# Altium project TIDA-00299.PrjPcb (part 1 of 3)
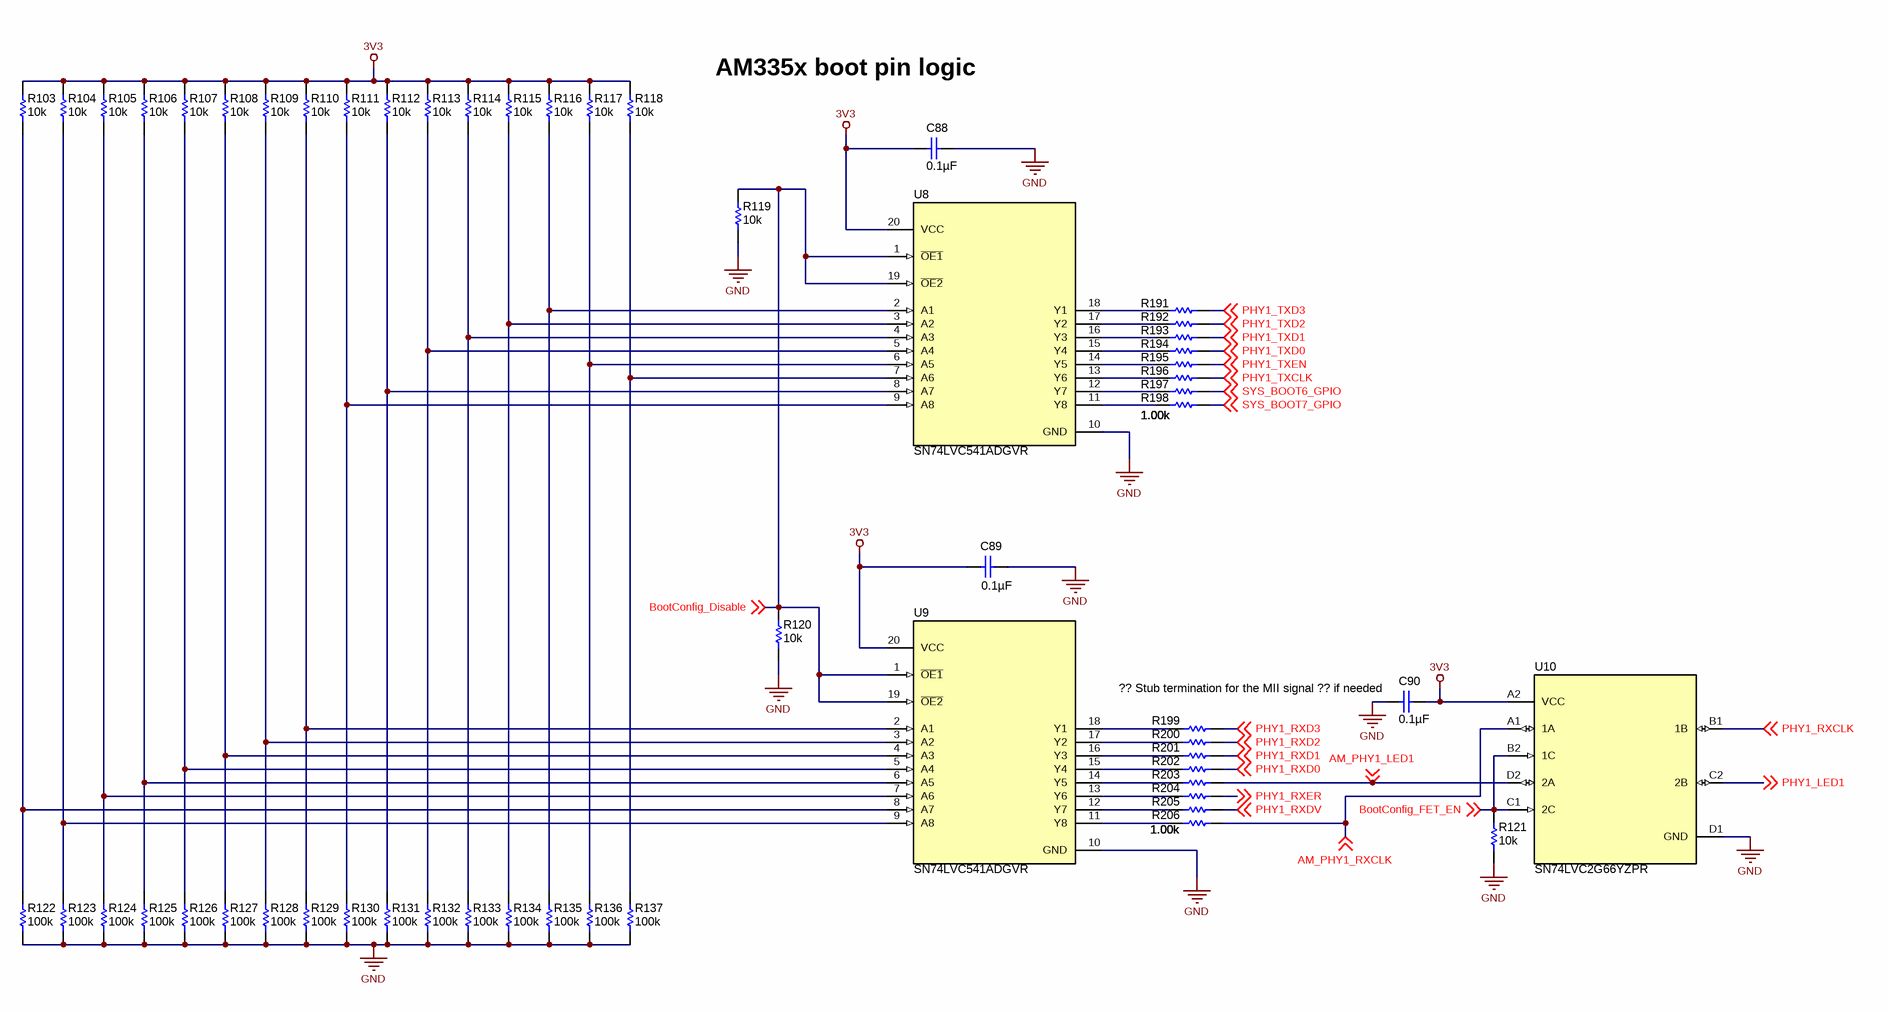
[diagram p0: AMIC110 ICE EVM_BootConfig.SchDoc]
TID: TIDA-00299; TechSupport: http://www.ti.com/support; SCH_Rev: E2.1; PRJ_Title1: Multi-Protocol Industrial Ethernet Reference Design; PRJ_Title: Cost Optimized Robust EtherCAT Slave and; PRJ_Number: TIDA-00299; PRJ_Engineer: Mogensen/Staebler; PRJ_Customer: Public Release; PCB_Rev: E2; PCB_Layout: Klaus Hacker; EVM_Orderable: N/A; CopyrightYear: 2017
10 sheets, 504 parts. Net scope: global (net labels, ports and power ports of the same name join across sheets).
Board file: MS_TI_AMIC110_ICE_EVM_BRD_REV1.1.PcbDoc
Sheets:
  AMIC110 ICE EVM_BootConfig.SchDoc
  AMIC110 ICE EVM_CS.SchDoc
  AMIC110 ICE EVM_HW.SchDoc
  AMIC110 ICE EVM_Interfaces.SchDoc
  AMIC110 ICE EVM_Led.SchDoc
  AMIC110 ICE EVM_Memory.SchDoc
  AMIC110 ICE EVM_PHY.SchDoc
  AMIC110 ICE EVM_Power.SchDoc
  AMIC110 ICE EVM_PS.SchDoc
  AMIC110 ICE EVM_SC_0.SchDoc

## Sheet AMIC110 ICE EVM_BootConfig.SchDoc
size 431 x 279 mm; Date: Not shown in title block; ApprovedBy: Not shown in title block; CheckedBy: Not shown in title block; Author: Not shown in title block; CompanyName: Not shown in title block; Engineer: Not shown in title block; Organization: Not shown in title block; Address1: Not shown in title block; Address2: Not shown in title block; Address3: Not shown in title block; Address4: Not shown in title block; DocumentNumber: 1; Revision: Use project parameter SCH_Rev; SheetNumber: 9; SheetTotal: 1; PageSetup: Record=PageOptions¦CenterHorizontal=True¦CenterVertical=True¦PrintScale=1.00¦XCorrection=1.00¦YCorrection=1.00¦PrintKind=0¦BorderSize=5000000¦LeftOffset=0¦BottomOffset=0¦Orientation=2¦PaperLength=1000¦PaperWidth=1000¦Scale=100¦PaperSource=15¦PrintQuality=600¦MediaType=1¦DitherType=10¦PaperKind=Letter¦PrintScaleMode=1

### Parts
C88  ValueDisplayed: 0.1µF  [0402]  (hidden comment: 885012205037)
C89  ValueDisplayed: 0.1µF  [0402L]  (hidden comment: 885012205037)
C90  ValueDisplayed: 0.1µF  [0402L]  (hidden comment: 885012205037)
R103  ValueDisplayed: 10k  [0402L]  (hidden comment: CRCW040210K0JNED)
R104  ValueDisplayed: 10k  [0402L]  (hidden comment: CRCW040210K0JNED)
R105  ValueDisplayed: 10k  [0402L]  (hidden comment: CRCW040210K0JNED)
R106  ValueDisplayed: 10k  [0402L]  (hidden comment: CRCW040210K0JNED)
R107  ValueDisplayed: 10k  [0402L]  (hidden comment: CRCW040210K0JNED)
R108  ValueDisplayed: 10k  [0402L]  (hidden comment: CRCW040210K0JNED)
R109  ValueDisplayed: 10k  [0402L]  (hidden comment: CRCW040210K0JNED)
R110  ValueDisplayed: 10k  [0402L]  (hidden comment: CRCW040210K0JNED)
R111  ValueDisplayed: 10k  [0402L]  (hidden comment: CRCW040210K0JNED)
R112  ValueDisplayed: 10k  [0402L]  (hidden comment: CRCW040210K0JNED)
R113  ValueDisplayed: 10k  [0402L]  (hidden comment: CRCW040210K0JNED)
R114  ValueDisplayed: 10k  [0402L]  (hidden comment: CRCW040210K0JNED)
R115  ValueDisplayed: 10k  [0402L]  (hidden comment: CRCW040210K0JNED)
R116  ValueDisplayed: 10k  [0402L]  (hidden comment: CRCW040210K0JNED)
R117  ValueDisplayed: 10k  [0402L]  (hidden comment: CRCW040210K0JNED)
R118  ValueDisplayed: 10k  [0402L]  (hidden comment: CRCW040210K0JNED)
R119  ValueDisplayed: 10k  [0402]  (hidden comment: CRCW040210K0JNED)
R120  ValueDisplayed: 10k  [0402L]  (hidden comment: CRCW040210K0JNED)
R121  ValueDisplayed: 10k  [0402L]  (hidden comment: CRCW040210K0JNED)
R122  ValueDisplayed: 100k  [0402L]  (hidden comment: CRCW0402100KJNED)
R123  ValueDisplayed: 100k  [0402L]  (hidden comment: CRCW0402100KJNED)
R124  ValueDisplayed: 100k  [0402L]  (hidden comment: CRCW0402100KJNED)
R125  ValueDisplayed: 100k  [0402L]  (hidden comment: CRCW0402100KJNED)
R126  ValueDisplayed: 100k  [0402L]  (hidden comment: CRCW0402100KJNED)
R127  ValueDisplayed: 100k  [0402L]  (hidden comment: CRCW0402100KJNED)
R128  ValueDisplayed: 100k  [0402L]  (hidden comment: CRCW0402100KJNED)
R129  ValueDisplayed: 100k  [0402L]  (hidden comment: CRCW0402100KJNED)
R130  ValueDisplayed: 100k  [0402L]  (hidden comment: CRCW0402100KJNED)
R131  ValueDisplayed: 100k  [0402L]  (hidden comment: CRCW0402100KJNED)
R132  ValueDisplayed: 100k  [0402L]  (hidden comment: CRCW0402100KJNED)
R133  ValueDisplayed: 100k  [0402L]  (hidden comment: CRCW0402100KJNED)
R134  ValueDisplayed: 100k  [0402L]  (hidden comment: CRCW0402100KJNED)
R135  ValueDisplayed: 100k  [0402L]  (hidden comment: CRCW0402100KJNED)
R136  ValueDisplayed: 100k  [0402L]  (hidden comment: CRCW0402100KJNED)
R137  ValueDisplayed: 100k  [0402L]  (hidden comment: CRCW0402100KJNED)
R191  ValueDisplayed: 1.00k  [0201L]  (hidden comment: CRCW02011K00FKED)
R192  ValueDisplayed: 1.00k  [0201L]  (hidden comment: CRCW02011K00FKED)
R193  ValueDisplayed: 1.00k  [0201L]  (hidden comment: CRCW02011K00FKED)
R194  ValueDisplayed: 1.00k  [0201L]  (hidden comment: CRCW02011K00FKED)
R195  ValueDisplayed: 1.00k  [0201L]  (hidden comment: CRCW02011K00FKED)
R196  ValueDisplayed: 1.00k  [0201L]  (hidden comment: CRCW02011K00FKED)
R197  ValueDisplayed: 1.00k  [0201L]  (hidden comment: CRCW02011K00FKED)
R198  ValueDisplayed: 1.00k  [0201L]  (hidden comment: CRCW02011K00FKED)
R199  ValueDisplayed: 1.00k  [0201L]  (hidden comment: CRCW02011K00FKED)
R200  ValueDisplayed: 1.00k  [0201L]  (hidden comment: CRCW02011K00FKED)
R201  ValueDisplayed: 1.00k  [0201L]  (hidden comment: CRCW02011K00FKED)
R202  ValueDisplayed: 1.00k  [0201L]  (hidden comment: CRCW02011K00FKED)
R203  ValueDisplayed: 1.00k  [0201L]  (hidden comment: CRCW02011K00FKED)
R204  ValueDisplayed: 1.00k  [0201L]  (hidden comment: CRCW02011K00FKED)
R205  ValueDisplayed: 1.00k  [0201L]  (hidden comment: CRCW02011K00FKED)
R206  ValueDisplayed: 1.00k  [0201L]  (hidden comment: CRCW02011K00FKED)
U8  SN74LVC541ADGVR  [DGV0020A_L]
U9  SN74LVC541ADGVR  [DGV0020A_L]
U10  SN74LVC2G66YZPR  [YZP0008ADAD]

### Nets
3V3: C88.1 C89.2 C90.2 R103.2 R104.2 R105.2 R106.2 R107.2 R108.2 R109.2 R110.2 R111.2 R112.2 R113.2 R114.2 R115.2 R116.2 R117.2 R118.2 U8.20(VCC) U9.20(VCC) U10.A2(VCC)
GND: C88.2 C89.1 C90.1 R119.1 R120.1 R121.1 R122.1 R123.1 R124.1 R125.1 R126.1 R127.1 R128.1 R129.1 R130.1 R131.1 R132.1 R133.1 R134.1 R135.1 R136.1 R137.1 U8.10(GND) U9.10(GND) U10.D1(GND)
AM_PHY1_LED1: R203.2 U10.D2(2A) ; off-sheet AM_PHY1_LED1
AM_PHY1_RXCLK: R206.2 U10.A1(1A) ; off-sheet AM_PHY1_RXCLK
BootConfig_Disable: R119.2 R120.2 U8.1(~{OE1}) U8.19(~{OE2}) U9.1(~{OE1}) U9.19(~{OE2}) ; off-sheet BootConfig_Disable
BootConfig_FET_EN: R121.2 U10.B2(1C) U10.C1(2C) ; off-sheet BootConfig_FET_EN
PHY1_LED1: U10.C2(2B) ; off-sheet PHY1_LED1
PHY1_RXCLK: U10.B1(1B) ; off-sheet PHY1_RXCLK
PHY1_RXD0: R202.2 ; off-sheet PHY1_RXD0
PHY1_RXD1: R201.2 ; off-sheet PHY1_RXD1
PHY1_RXD2: R200.2 ; off-sheet PHY1_RXD2
PHY1_RXD3: R199.2 ; off-sheet PHY1_RXD3
PHY1_RXDV: R205.2 ; off-sheet PHY1_RXDV
PHY1_RXER: R204.2 ; off-sheet PHY1_RXER
PHY1_TXCLK: R196.2 ; off-sheet PHY1_TXCLK
PHY1_TXD0: R194.2 ; off-sheet PHY1_TXD0
PHY1_TXD1: R193.2 ; off-sheet PHY1_TXD1
PHY1_TXD2: R192.2 ; off-sheet PHY1_TXD2
PHY1_TXD3: R191.2 ; off-sheet PHY1_TXD3
PHY1_TXEN: R195.2 ; off-sheet PHY1_TXEN
SYS_BOOT6_GPIO: R197.2 ; off-sheet SYS_BOOT6_GPIO
SYS_BOOT7_GPIO: R198.2 ; off-sheet SYS_BOOT7_GPIO
NetR103_1: R103.1 R122.2 U9.8(A7)
NetR104_1: R104.1 R123.2 U9.9(A8)
NetR105_1: R105.1 R124.2 U9.7(A6)
NetR106_1: R106.1 R125.2 U9.6(A5)
NetR107_1: R107.1 R126.2 U9.5(A4)
NetR108_1: R108.1 R127.2 U9.4(A3)
NetR109_1: R109.1 R128.2 U9.3(A2)
NetR110_1: R110.1 R129.2 U9.2(A1)
NetR111_1: R111.1 R130.2 U8.9(A8)
NetR112_1: R112.1 R131.2 U8.8(A7)
NetR113_1: R113.1 R132.2 U8.5(A4)
NetR114_1: R114.1 R133.2 U8.4(A3)
NetR115_1: R115.1 R134.2 U8.3(A2)
NetR116_1: R116.1 R135.2 U8.2(A1)
NetR117_1: R117.1 R136.2 U8.6(A5)
NetR118_1: R118.1 R137.2 U8.7(A6)
NetR191_1: R191.1 U8.18(Y1)
NetR192_1: R192.1 U8.17(Y2)
NetR193_1: R193.1 U8.16(Y3)
NetR194_1: R194.1 U8.15(Y4)
NetR195_1: R195.1 U8.14(Y5)
NetR196_1: R196.1 U8.13(Y6)
NetR197_1: R197.1 U8.12(Y7)
NetR198_1: R198.1 U8.11(Y8)
NetR199_1: R199.1 U9.18(Y1)
NetR200_1: R200.1 U9.17(Y2)
NetR201_1: R201.1 U9.16(Y3)
NetR202_1: R202.1 U9.15(Y4)
NetR203_1: R203.1 U9.14(Y5)
NetR204_1: R204.1 U9.13(Y6)
NetR205_1: R205.1 U9.12(Y7)
NetR206_1: R206.1 U9.11(Y8)

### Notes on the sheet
- AM335x boot pin logic
- (near C90) ?? Stub termination for the MII signal ?? if needed

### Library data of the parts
C88 = 885012205037: CAP, CERM, 0.1 µF, 16 V, +/- 10%, X7R, 0402; Manufacturer: Wurth Elektronik; Polarized: N; CompType: Capacitor; Value: 0.1uF; U/M: EA; Cap_F: 0.0000001; Tolerance_%: 10; Value1: Unknown; VDC_V: 16; Value2: 16V; TaMin_C: -55; TaMax_C: 125; AEC Category: Q200
C89 C90 = 885012205037: CAP, CERM, 0.1 µF, 16 V, +/- 10%, X7R, 0402; Manufacturer: Wurth Elektronik; Polarized: N; CompType: Capacitor; Value: 0.1uF; U/M: EA; Cap_F: 0.0000001; Tolerance_%: 10; Value1: Unknown; VDC_V: 16; Value2: 16V; TaMin_C: -55; TaMax_C: 125; Cap_Case: 0402; AEC Category: Q200
R103-R118 R121 = CRCW040210K0JNED: RES, 10 k, 5%, 0.063 W, 0402; Manufacturer: Vishay-Dale; CompType: Resistor; Value: 10k; Res_ohm: 10000; Value_Code: 10k0; Tolerance_%: 5; Power_W: 0.063; Value2: 0.063W; VDC_V: 50; TempCo: 200 ppm/C; EIA_Code: E24; U/M: EA
R119 R120 = CRCW040210K0JNED: RES, 10 k, 5%, 0.063 W, 0402; Manufacturer: Vishay-Dale; CompType: Resistor; Value: 10k; Res_ohm: 10000; Value_Code: 10k0; Tolerance_%: 5; Power_W: 0.063; Value2: 0.063W; VDC_V: 50; TempCo: 200 ppm/C; EIA_Code: E24; U/M: EA; AEC Category: Q200
R122-R137 = CRCW0402100KJNED: RES, 100 k, 5%, 0.063 W, 0402; Manufacturer: Vishay-Dale; CompType: Resistor; Value: 100k; Res_ohm: 100000; Tolerance_%: 5; Power_W: 0.063; Value2: 0.063W; VDC_V: 50; TempCo: 200 ppm/C; EIA_Code: E24; U/M: EA
R191-R206 = CRCW02011K00FKED: RES, 1.00 k, 1%, 0.05 W, 0201; Manufacturer: Vishay-Dale; CompType: Resistor; Value: 1.00k; Res_ohm: 1000; Value_Code: 1k00; Tolerance_%: 1; Power_W: 0.05; Value2: 0.05W; VDC_V: 30; TempCo: 100 ppm/C; SizeArea_mm2: 0.18; SizeAreaWB_mm2: 2.08; SizeX_mm: 0.6; SizeY_mm: 0.3; SizeZ_mm: 0.26; EIA_Code: E96; U/M: EA; AEC Category: Q200
U8 U9 = SN74LVC541ADGVR: Octal Buffers/Drivers With 3-State Outputs, DGV0020A; Manufacturer: Texas Instruments; SymbolCreator: Altium; CompType: IC; U/M: EA
U10 = SN74LVC2G66YZPR: Dual Bilateral Analog Switch, YZP0008ADAD; Manufacturer: Texas Instruments; SymbolCreator: Altium; CompType: IC; U/M: EA

## Sheet AMIC110 ICE EVM_CS.SchDoc
size 431 x 279 mm; Date: Not shown in title block; ApprovedBy: Not shown in title block; CheckedBy: Not shown in title block; Author: Not shown in title block; CompanyName: Not shown in title block; DrawnBy: K. Mogensen; Engineer: Not shown in title block; Organization: Not shown in title block; Address1: Not shown in title block; Address2: Not shown in title block; Address3: Not shown in title block; Address4: Not shown in title block; DocumentNumber: 1; Revision: Use project parameter SCH_Rev; SheetNumber: 1; SheetTotal: 1; PageSetup: Record=PageOptions¦CenterHorizontal=True¦CenterVertical=True¦PrintScale=1.00¦XCorrection=1.00¦YCorrection=1.00¦PrintKind=0¦BorderSize=5000000¦LeftOffset=0¦BottomOffset=0¦Orientation=2¦PaperLength=1000¦PaperWidth=1000¦Scale=100¦PaperSource=15¦PrintQuality=600¦MediaType=1¦DitherType=10¦PaperKind=Letter¦PrintScaleMode=1
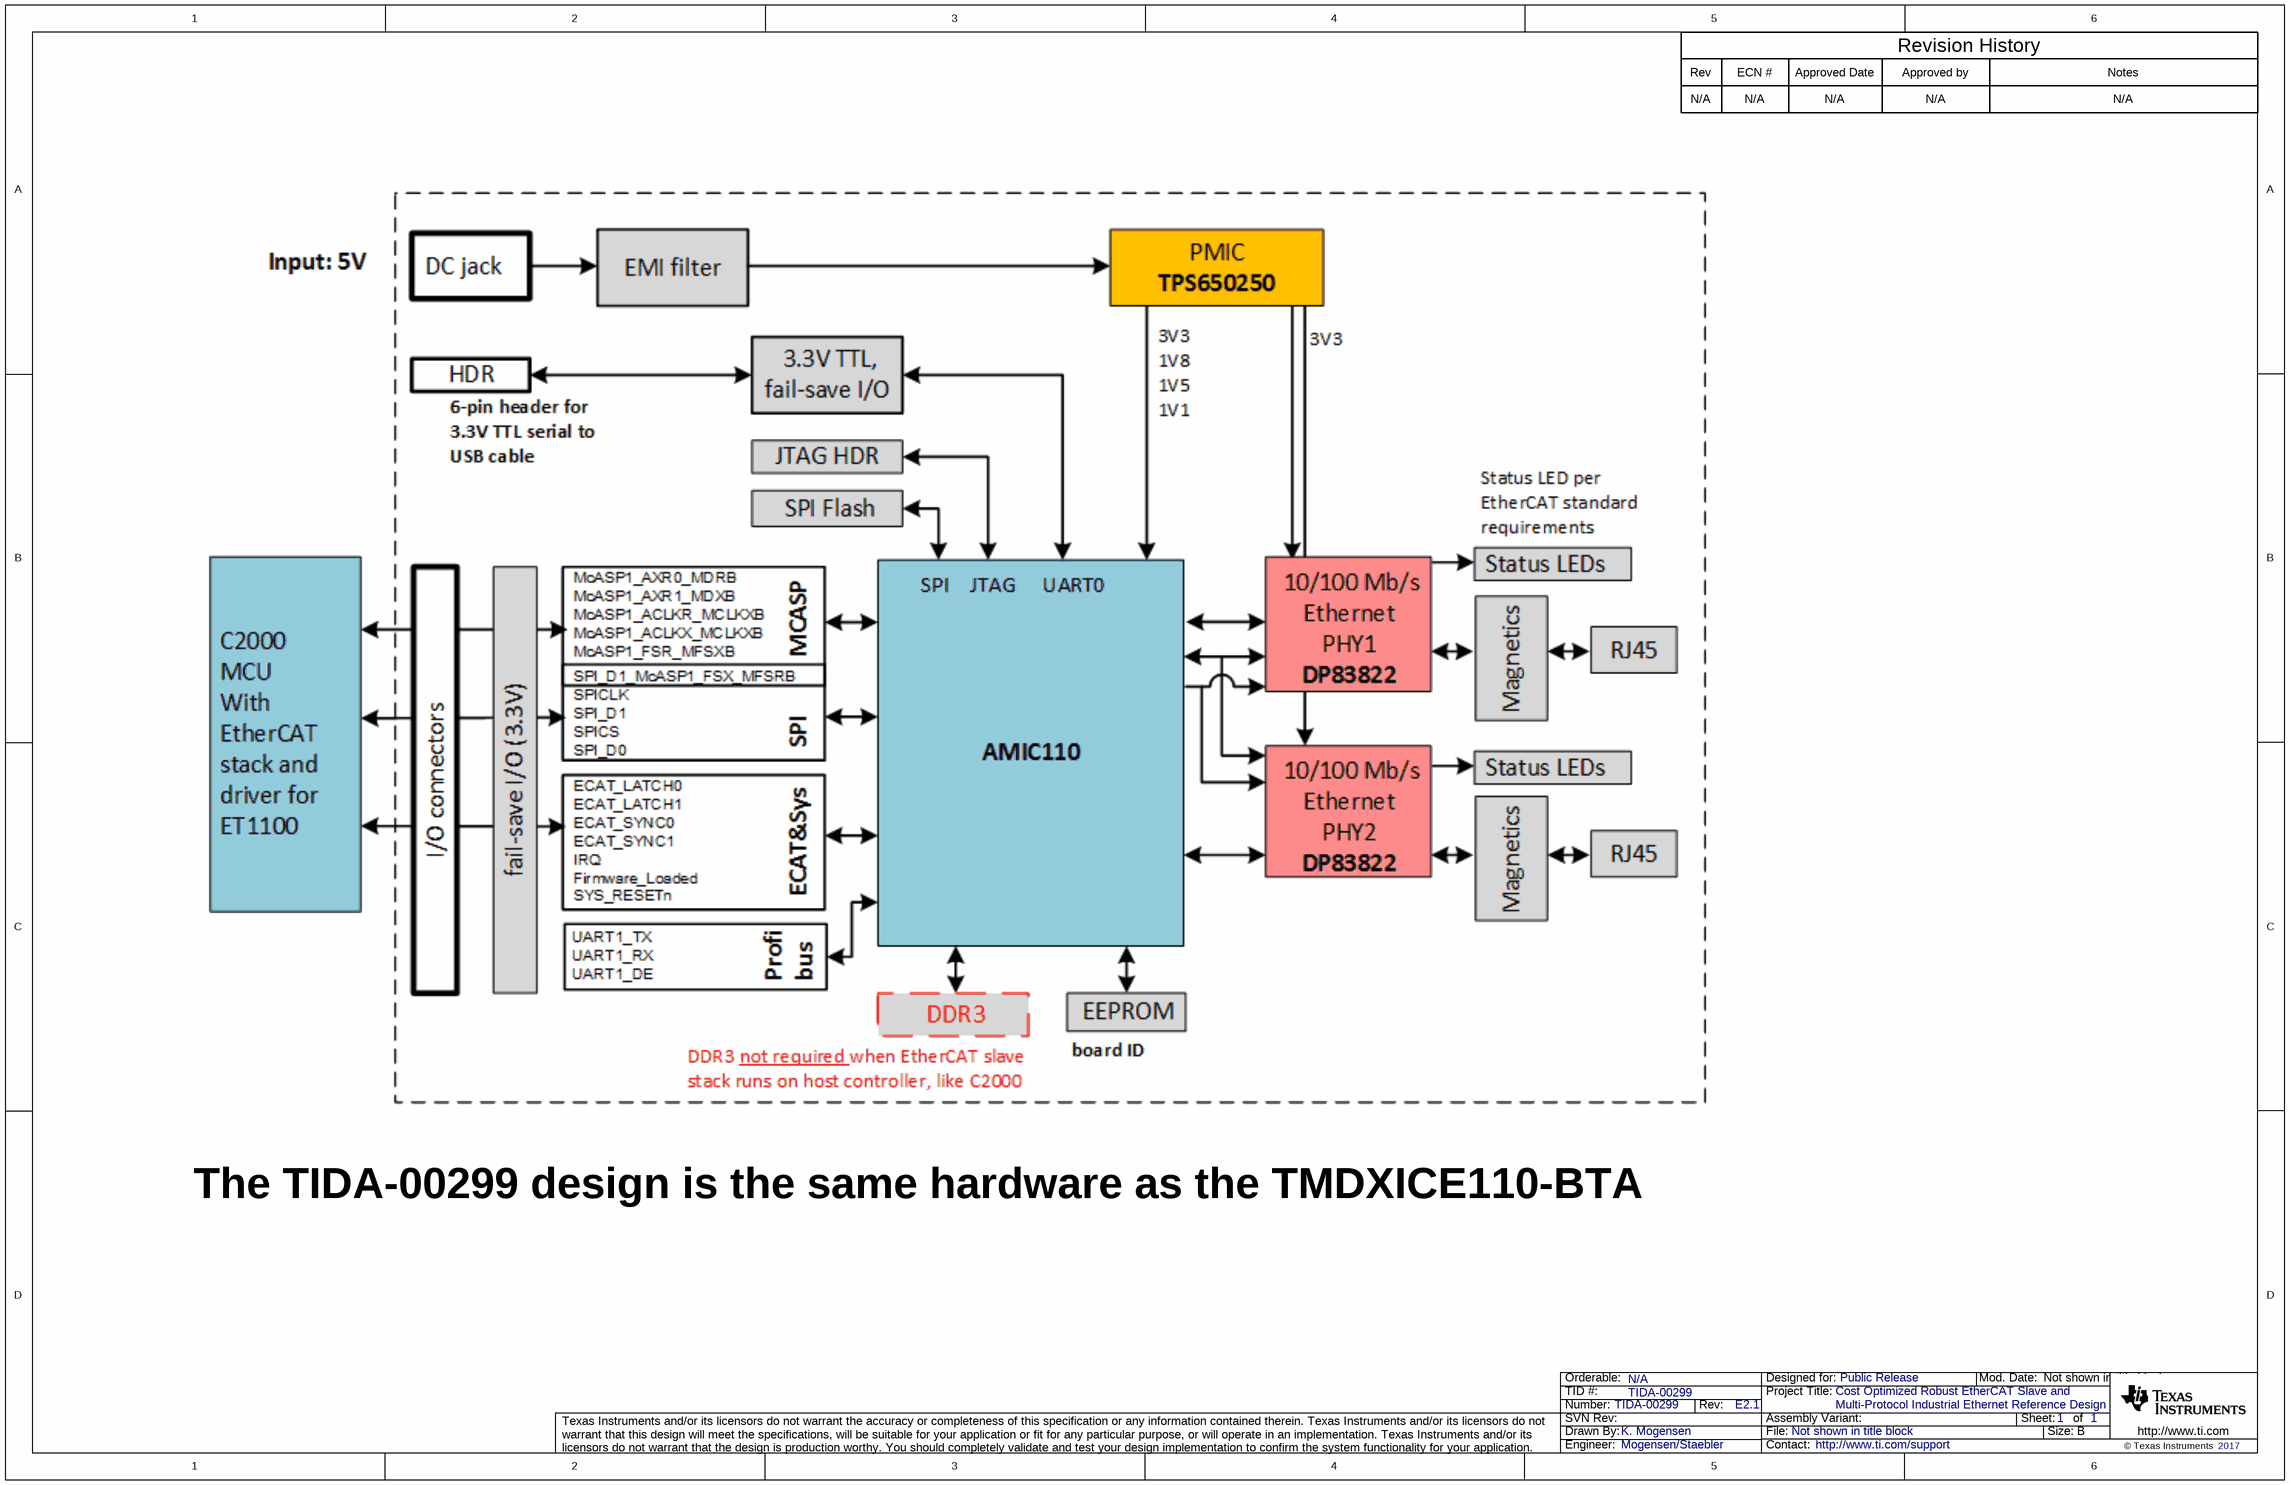
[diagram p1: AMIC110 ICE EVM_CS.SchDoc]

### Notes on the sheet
- Rev
- N/A
- ECN #
- Approved Date
- Approved by
- Revision History
- Notes
- The TIDA-00299 design is the same hardware as the TMDXICE110-BTA

## Sheet AMIC110 ICE EVM_HW.SchDoc
size 431 x 279 mm; Date: Not shown in title block; ApprovedBy: Not shown in title block; CheckedBy: Not shown in title block; Author: Not shown in title block; CompanyName: Not shown in title block; Engineer: Not shown in title block; Organization: Not shown in title block; Address1: Not shown in title block; Address2: Not shown in title block; Address3: Not shown in title block; Address4: Not shown in title block; DocumentNumber: 1; Revision: Use project parameter SCH_Rev; SheetNumber: 2; SheetTotal: 1; PageSetup: Record=PageOptions¦CenterHorizontal=True¦CenterVertical=True¦PrintScale=1.00¦XCorrection=1.00¦YCorrection=1.00¦PrintKind=0¦BorderSize=5000000¦LeftOffset=0¦BottomOffset=0¦Orientation=2¦PaperLength=1000¦PaperWidth=1000¦Scale=100¦PaperSource=15¦PrintQuality=600¦MediaType=1¦DitherType=10¦PaperKind=Letter¦PrintScaleMode=1
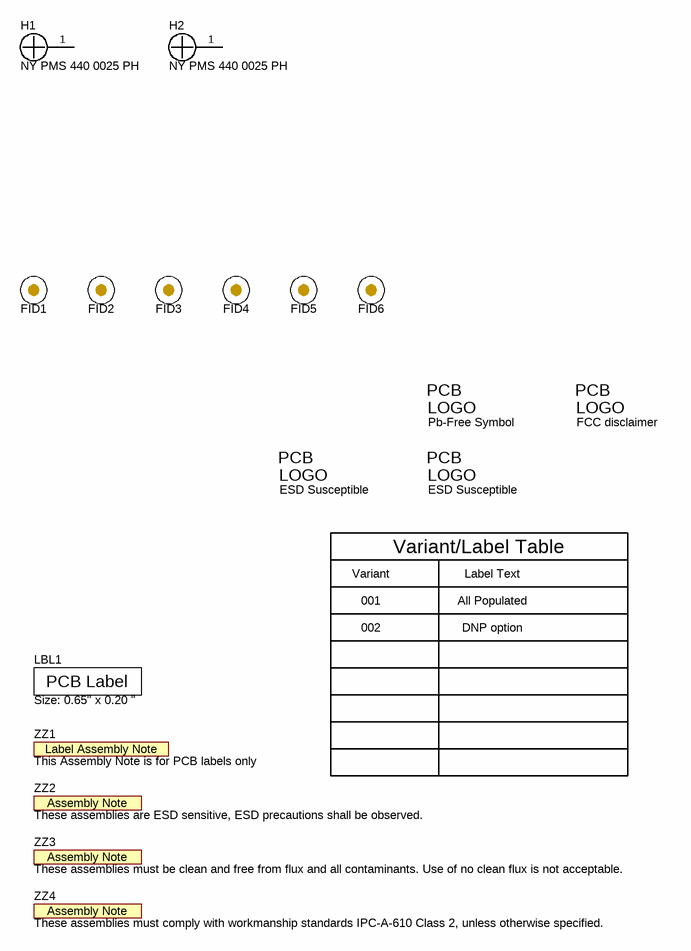
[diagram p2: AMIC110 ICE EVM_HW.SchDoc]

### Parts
FID1  Fiducial  [Fiducial10-20]  (value not drawn)
FID2  Fiducial  [Fiducial10-20]  (value not drawn)
FID3  Fiducial  [Fiducial10-20]  (value not drawn)
FID4  Fiducial  [Fiducial10-20]  (value not drawn)
FID5  Fiducial  [Fiducial10-20]  (value not drawn)
FID6  Fiducial  [Fiducial10-20]  (value not drawn)
H1  NY PMS 440 0025 PH  [NY PMS 440 0025 PH]
H2  NY PMS 440 0025 PH  [NY PMS 440 0025 PH]
LBL1  Size: 0.65" x 0.20 "  [Label_650x200]
Logo2  Pb-Free Symbol  [Pb-Free_Overlay_Small]  (no BOM)
Logo3  FCC disclaimer  [FCC_disclaimer]  (no BOM)
Logo4  ESD Susceptible  [ESD_Overlay_Small]  (no BOM)
Logo5  ESD Susceptible  [ESD_Overlay_Small]  (no BOM)
ZZ1  This Assembly Note is for PCB labels only  [AssemblyNoteLabel]  (no BOM)
ZZ2  These assemblies are ESD sensitive, ESD precautions shall be observed.  [AssemblyNote]  (no BOM)
ZZ3  These assemblies must be clean and free from flux and all contaminants. Use of no clean flux is not acceptable.  [AssemblyNote]  (no BOM)
ZZ4  These assemblies must comply with workmanship standards IPC-A-610 Class 2, unless otherwise specified.  [AssemblyNote]  (no BOM)

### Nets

Not connected (* = marked no-connect by the designer): H1 1; H2 1

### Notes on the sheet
- Variant
- Variant/Label Table
- Label Text
- 001
- 002
- All Populated
- DNP option

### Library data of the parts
FID1-FID6 = Fiducial: Fiducial mark.  There is nothing to buy or mount.; SymbolCreator: codlsc
H1 H2 = NY PMS 440 0025 PH: Machine Screw, Round, #4-40 x 1/4, Nylon, Philips panhead; Manufacturer: B&F Fastener Supply; CompType: Hardware; SymbolCreator: codlsc; U/M: EA
LBL1 = THT-14-423-10: Thermal Transfer Printable Labels, 0.650" W x 0.200" H - 10,000 per roll; Manufacturer: Brady; SymbolCreator: a0412235; CompType: Label
Logo2 = Pb-Free: SymbolCreator: a0412235
Logo3 = FCC_disclaimer: SymbolCreator: codlsc
Logo4 Logo5 = ESD_Susceptible: ESD Susceptible Symbol; SymbolCreator: a0412235
ZZ1 = AssemblyNoteLabel: SymbolCreator: a0412235
ZZ2-ZZ4 = AssemblyNote: SymbolCreator: codlsc

## Sheet AMIC110 ICE EVM_Interfaces.SchDoc
size 431 x 279 mm; Date: Not shown in title block; ApprovedBy: Not shown in title block; CheckedBy: Not shown in title block; Author: Not shown in title block; CompanyName: Not shown in title block; Engineer: Not shown in title block; Organization: Not shown in title block; Address1: Not shown in title block; Address2: Not shown in title block; Address3: Not shown in title block; Address4: Not shown in title block; DocumentNumber: 1; Revision: Use project parameter SCH_Rev; SheetNumber: 7; SheetTotal: 1; PageSetup: Record=PageOptions¦CenterHorizontal=True¦CenterVertical=True¦PrintScale=1.00¦XCorrection=1.00¦YCorrection=1.00¦PrintKind=0¦BorderSize=5000000¦LeftOffset=0¦BottomOffset=0¦Orientation=2¦PaperLength=1000¦PaperWidth=1000¦Scale=100¦PaperSource=15¦PrintQuality=600¦MediaType=1¦DitherType=10¦PaperKind=Letter¦PrintScaleMode=1
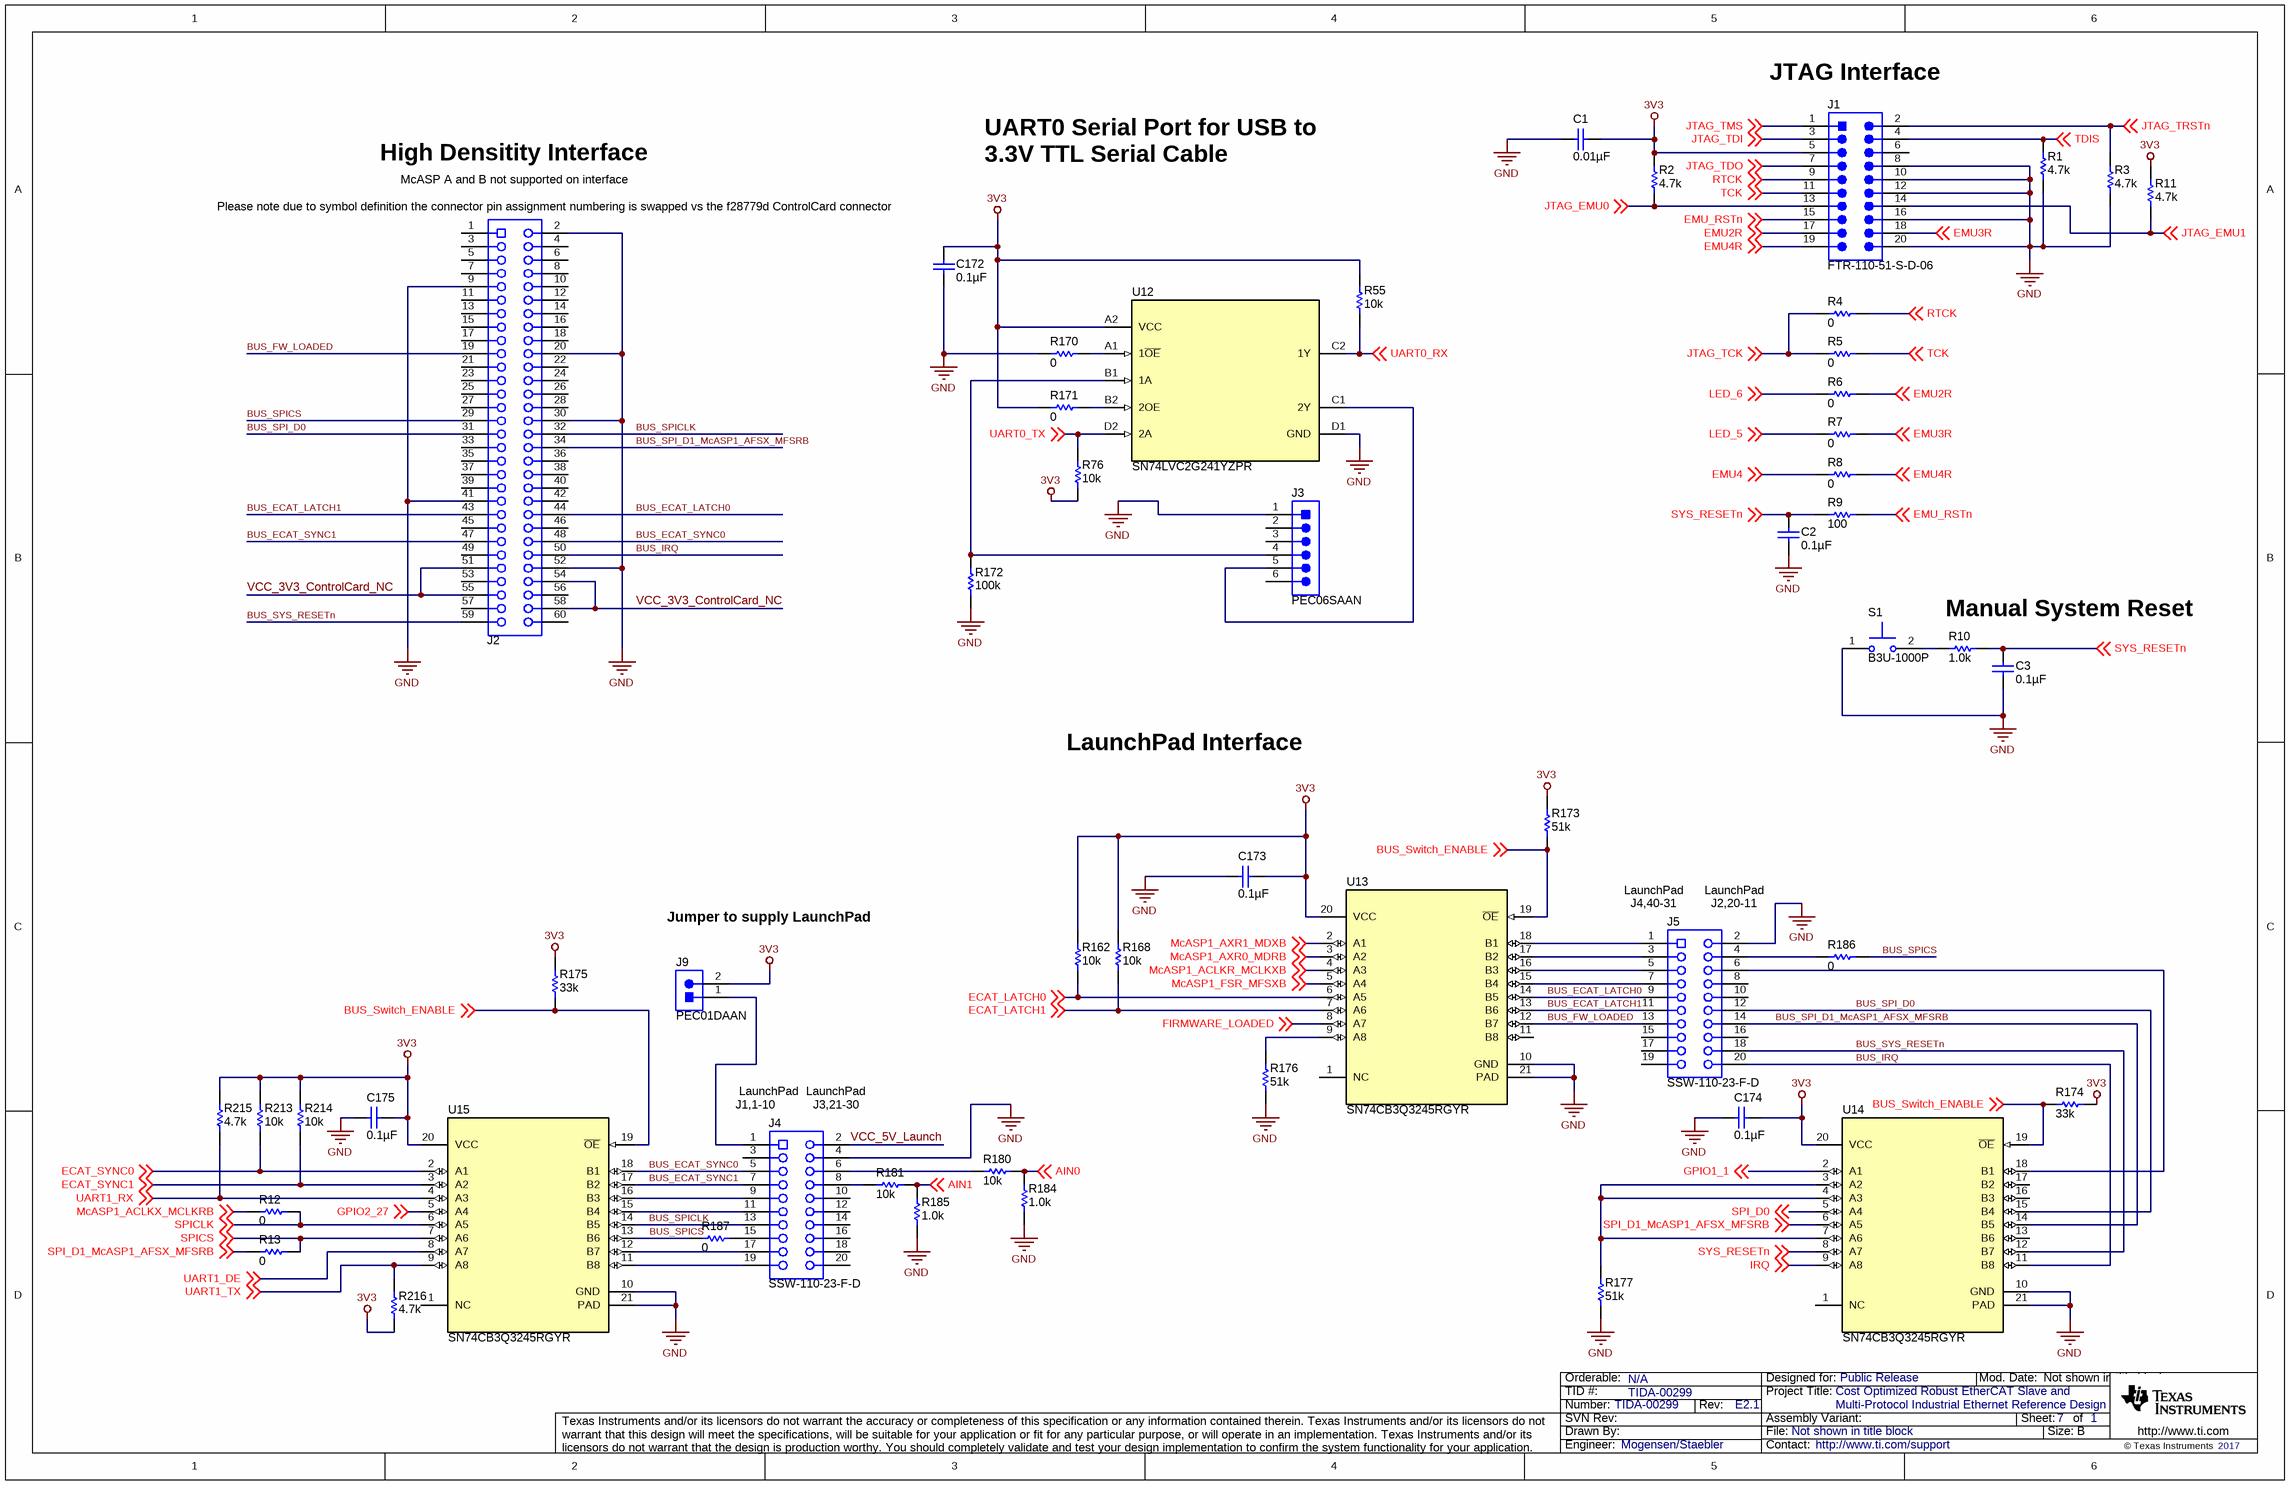
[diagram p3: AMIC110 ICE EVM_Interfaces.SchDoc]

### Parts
C1  ValueDisplayed: 0.01µF  [0201]  (hidden comment: GRM033R71A103KA01D)
C2  ValueDisplayed: 0.1µF  [0402]  (hidden comment: GRM155R71A104KA01D)
C3  ValueDisplayed: 0.1µF  [0402]  (hidden comment: GRM155R70J104KA01D)
C172  ValueDisplayed: 0.1µF  [0402]  (hidden comment: GRM155R71A104KA01D)
C173  ValueDisplayed: 0.1µF  [0402]  (hidden comment: GRM155R71A104KA01D)
C174  ValueDisplayed: 0.1µF  [0402]  (hidden comment: GRM155R71A104KA01D)
C175  ValueDisplayed: 0.1µF  [0402]  (hidden comment: GRM155R71A104KA01D)
J1  FTR-110-51-S-D-06  [Samtec_FTR-110-51-x-D-06]
J2  DF40HC(4.0)-60DS-0.4V(51)  [Hirose_DF40HC-4_0-60DS-0_4V]  (value not drawn)
J3  PEC06SAAN  [Sullins_PEC06SAAN]
J4  SSW-110-23-F-D  [CONN_SSW-110-23-F-D]
J5  SSW-110-23-F-D  [CONN_SSW-110-23-F-D]
J9  PEC01DAAN  [Sullins_PxC01DAAN]
R1  ValueDisplayed: 4.7k  [0402]  (hidden comment: CRCW04024K70JNED)
R2  ValueDisplayed: 4.7k  [0402]  (hidden comment: CRCW04024K70JNED)
R3  ValueDisplayed: 4.7k  [0402]  (hidden comment: CRCW04024K70JNED)
R4  ValueDisplayed: 0  [0402]  (hidden comment: CRCW04020000Z0ED)
R5  ValueDisplayed: 0  [0402]  (hidden comment: CRCW04020000Z0ED)
R6  ValueDisplayed: 0  [0402]  (hidden comment: CRCW04020000Z0ED)
R7  ValueDisplayed: 0  [0402]  (hidden comment: CRCW04020000Z0ED)
R8  ValueDisplayed: 0  [0402]  (hidden comment: CRCW04020000Z0ED)
R9  ValueDisplayed: 100  [0402]  (hidden comment: CRCW0402100RJNED)
R10  ValueDisplayed: 1.0k  [0402]  (hidden comment: CRCW04021K00JNED)
R11  ValueDisplayed: 4.7k  [0402]  (hidden comment: CRCW04024K70JNED)
R12  ValueDisplayed: 0  [0402L]  (hidden comment: CRCW04020000Z0ED)
R13  ValueDisplayed: 0  [0402L]  (hidden comment: CRCW04020000Z0ED)
R55  ValueDisplayed: 10k  [0402L]  (hidden comment: CRCW040210K0JNED)
R76  ValueDisplayed: 10k  [0402L]  (hidden comment: CRCW040210K0JNED)
R162  ValueDisplayed: 10k  [0402L]  (hidden comment: CRCW040210K0JNED)
R168  ValueDisplayed: 10k  [0402L]  (hidden comment: CRCW040210K0JNED)
R170  ValueDisplayed: 0  [0402L]  (hidden comment: CRCW04020000Z0ED)
R171  ValueDisplayed: 0  [0402L]  (hidden comment: CRCW04020000Z0ED)
R172  ValueDisplayed: 100k  [0402L]  (hidden comment: CRCW0402100KJNED)
R173  ValueDisplayed: 51k  [0402]  (hidden comment: CRCW040251K0JNED)
R174  ValueDisplayed: 33k  [0402]  (hidden comment: CRCW040233K0JNED)
R175  ValueDisplayed: 33k  [0402]  (hidden comment: CRCW040233K0JNED)
R176  ValueDisplayed: 51k  [0402]  (hidden comment: CRCW040251K0JNED)
R177  ValueDisplayed: 51k  [0402]  (hidden comment: CRCW040251K0JNED)
R180  ValueDisplayed: 10k  [0603]  (hidden comment: CRCW060310K0JNEA)
R181  ValueDisplayed: 10k  [0603]  (hidden comment: CRCW060310K0JNEA)
R184  ValueDisplayed: 1.0k  [0603]  (hidden comment: CRCW06031K00JNEA)
R185  ValueDisplayed: 1.0k  [0603]  (hidden comment: CRCW06031K00JNEA)
R186  ValueDisplayed: 0  [0402L]  (hidden comment: CRCW04020000Z0ED)
R187  ValueDisplayed: 0  [0402L]  (hidden comment: CRCW04020000Z0ED)
R213  ValueDisplayed: 10k  [0402L]  (hidden comment: CRCW040210K0JNED)
R214  ValueDisplayed: 10k  [0402L]  (hidden comment: CRCW040210K0JNED)
R215  ValueDisplayed: 4.7k  [0402L]  (hidden comment: CRCW04024K70JNED)
R216  ValueDisplayed: 4.7k  [0402L]  (hidden comment: CRCW04024K70JNED)
S1  B3U-1000P  [SW_B3U-1000P]
U12  SN74LVC2G241YZPR  [YZP0008ADAD]
U13  SN74CB3Q3245RGYR  [RGY0020A]
U14  SN74CB3Q3245RGYR  [RGY0020A]
U15  SN74CB3Q3245RGYR  [RGY0020A]

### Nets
3V3: C1.2 C172.2 C173.1 C174.1 C175.1 J1.5 J9.2 R2.2 R11.2 R55.2 R76.1 R162.1 R168.1 R171.1 R173.2 R174.1 R175.2 R213.1 R214.1 R215.2 R216.1 U12.A2(VCC) U13.20(VCC) U14.20(VCC) U15.20(VCC)
GND: C1.1 C2.1 C3.2 C172.1 C173.2 C174.2 C175.2 J1.8 J1.10 J1.12 J1.16 J1.20 J2.2 J2.9 J2.20 J2.30 J2.41 J2.52 J3.1 J4.4 J5.2 R1.1 R3.1 R170.1 R172.1 R176.1 R177.1 R184.1 R185.1 S1.1 U12.D1(GND) U13.10(GND) U13.21(PAD) U14.10(GND) U14.21(PAD) U15.10(GND) U15.21(PAD)
AIN0: R180.2 R184.2 ; off-sheet AIN0
AIN1: R181.2 R185.2 ; off-sheet AIN1
BUS_ECAT_LATCH0: J2.44 J5.9 U13.14(B5)
BUS_ECAT_LATCH1: J2.43 J5.11 U13.13(B6)
BUS_ECAT_SYNC0: J2.48 J4.5 U15.18(B1)
BUS_ECAT_SYNC1: J2.47 J4.7 U15.17(B2)
BUS_FW_LOADED: J2.19 J5.13 U13.12(B7)
BUS_IRQ: J2.50 J5.20 U14.11(B8)
BUS_SPI_D0: J2.31 J5.12 U14.15(B4)
BUS_SPI_D1_McASP1_AFSX_MFSRB: J2.34 J5.14 U14.14(B5)
BUS_SPICLK: J2.32 J4.13 U15.14(B5)
BUS_SPICS: J2.29 R186.2 R187.1 U15.13(B6)
BUS_Switch_ENABLE: R173.1 R174.2 R175.1 U13.19(~{OE}) U14.19(~{OE}) U15.19(~{OE}) ; off-sheet BUS_Switch_ENABLE
BUS_SYS_RESETn: J2.59 J5.18 U14.12(B7)
ECAT_LATCH0: R162.2 U13.6(A5) ; off-sheet ECAT_LATCH0
ECAT_LATCH1: R168.2 U13.7(A6) ; off-sheet ECAT_LATCH1
ECAT_SYNC0: R213.2 U15.2(A1) ; off-sheet ECAT_SYNC0
ECAT_SYNC1: R214.2 U15.3(A2) ; off-sheet ECAT_SYNC1
EMU2R: J1.17 R6.2 ; off-sheet EMU2R
EMU3R: J1.18 R7.2 ; off-sheet EMU3R
EMU4: R8.1 ; off-sheet EMU4
EMU4R: J1.19 R8.2 ; off-sheet EMU4R
EMU_RSTn: J1.15 R9.2 ; off-sheet EMU_RSTn
FIRMWARE_LOADED: U13.8(A7) ; off-sheet FIRMWARE_LOADED
GPIO1_1: U14.2(A1) ; off-sheet GPIO1_1
GPIO2_27: U15.5(A4) ; off-sheet GPIO2_27
IRQ: U14.9(A8) ; off-sheet IRQ
JTAG_EMU0: J1.13 R2.1 ; off-sheet JTAG_EMU0
JTAG_EMU1: J1.14 R11.1 ; off-sheet JTAG_EMU1
JTAG_TCK: R4.1 R5.1 ; off-sheet JTAG_TCK
JTAG_TDI: J1.3 ; off-sheet JTAG_TDI
JTAG_TDO: J1.7 ; off-sheet JTAG_TDO
JTAG_TMS: J1.1 ; off-sheet JTAG_TMS
JTAG_TRSTn: J1.2 R3.2 ; off-sheet JTAG_TRSTn
LED_5: R7.1 ; off-sheet LED_5
LED_6: R6.1 ; off-sheet LED_6
McASP1_ACLKR_MCLKXB: U13.4(A3) ; off-sheet McASP1_ACLKR_MCLKXB
McASP1_ACLKX_MCLKRB: R12.1 ; off-sheet McASP1_ACLKX_MCLKRB
McASP1_AXR0_MDRB: U13.3(A2) ; off-sheet McASP1_AXR0_MDRB
McASP1_AXR1_MDXB: U13.2(A1) ; off-sheet McASP1_AXR1_MDXB
McASP1_FSR_MFSXB: U13.5(A4) ; off-sheet McASP1_FSR_MFSXB
RTCK: J1.9 R4.2 ; off-sheet RTCK
SPI_D0: U14.5(A4) ; off-sheet SPI_D0
SPI_D1_McASP1_AFSX_MFSRB: R13.1 U14.6(A5) ; off-sheet SPI_D1_McASP1_AFSX_MFSRB
SPICLK: R12.2 U15.6(A5) ; off-sheet SPICLK
SPICS: R13.2 U15.7(A6) ; off-sheet SPICS
SYS_RESETn: C2.2 C3.1 R9.1 R10.1 U14.8(A7) ; off-sheet SYS_RESETn
TCK: J1.11 R5.2 ; off-sheet TCK
TDIS: J1.4 R1.2 ; off-sheet TDIS
UART0_RX: R55.1 U12.C2(1Y) ; off-sheet UART0_RX
UART0_TX: R76.2 U12.D2(2A) ; off-sheet UART0_TX
UART1_DE: U15.8(A7) ; off-sheet UART1_DE
UART1_RX: R215.1 U15.4(A3) ; off-sheet UART1_RX
UART1_TX: R216.2 U15.9(A8) ; off-sheet UART1_TX
VCC_3V3_ControlCard_NC: J2.51 J2.54 J2.55 J2.58
VCC_5V_Launch: J4.2
NetJ3_4: J3.4 R172.2 U12.B1(1A)
NetJ3_5: J3.5 U12.C1(2Y)
NetJ4_1: J4.1 J9.1
NetJ4_6: J4.6 R180.1
NetJ4_8: J4.8 R181.1
NetJ4_9: J4.9 U15.16(B3)
NetJ4_11: J4.11 U15.15(B4)
NetJ4_15: J4.15 R187.2
NetJ4_17: J4.17 U15.12(B7)
NetJ4_19: J4.19 U15.11(B8)
NetJ5_1: J5.1 U13.18(B1)
NetJ5_3: J5.3 U13.17(B2)
NetJ5_4: J5.4 R186.1
NetJ5_5: J5.5 U13.16(B3)
NetJ5_6: J5.6 U14.18(B1)
NetJ5_7: J5.7 U13.15(B4)
NetR10_2: R10.2 S1.2
NetR170_2: R170.2 U12.A1(1~{OE})
NetR171_2: R171.2 U12.B2(2OE)
NetR176_2: R176.2 U13.9(A8)
NetR177_2: R177.2 U14.3(A2) U14.4(A3) U14.7(A6)

Not connected (* = marked no-connect by the designer): J1 6; J2 1 3 4 5 6 7 8 10 11 12 13 14 15 16 17 18 21 22 23 24 25 26 27 28 33 35 36 37 38 39 40 42 45 46 49 53 56 57 60; J3 2 3 6; J4 3 10 12 14 16 18 20; J5 8 10 15 16 17 19; U13 1(NC) 11(B8); U14 1(NC) 13(B6) 16(B3) 17(B2); U15 1(NC)

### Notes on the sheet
- (near J1) JTAG Interface
- High Densitity Interface
- UART0 Serial Port for USB to 3.3V TTL Serial Cable
- (near J2) McASP A and B not supported on interface
- (near J2) Please note due to symbol definition the connector pin assignment numbering is swapped vs the f28779d ControlCard connector
- Manual System Reset
- LaunchPad Interface
- (near J5) LaunchPad
- (near J5) J4,40-31
- (near J5) J2,20-11
- Jumper to supply LaunchPad
- (near J4) J1,1-10
- (near J4) LaunchPad
- (near J4) J3,21-30

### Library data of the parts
C1 = GRM033R71A103KA01D: CAP, CERM, 0.01 µF, 10 V, +/- 10%, X7R, 0201; Manufacturer: MuRata; Polarized: N; CompType: Capacitor; Value: 0.01uF; U/M: EA; Cap_F: 0.00000001; Tolerance_%: 10; Value1: Unknown; Value2: 10V; TaMin_C: -55; TaMax_C: 125
C2 C172-C175 = GRM155R71A104KA01D: CAP, CERM, 0.1 µF, 10 V, +/- 10%, X7R, 0402; Manufacturer: MuRata; Polarized: N; CompType: Capacitor; Value: 0.1uF; U/M: EA; Cap_F: 0.0000001; Tolerance_%: 10; Value1: Unknown; Value2: 10V; TaMin_C: -55; TaMax_C: 125
C3 = GRM155R70J104KA01D: CAP, CERM, 0.1 µF, 6.3 V, +/- 10%, X7R, 0402; Manufacturer: MuRata; Polarized: N; CompType: Capacitor; Value: 0.1uF; U/M: EA; Cap_F: 0.0000001; Tolerance_%: 10; Value1: Unknown; VDC_V: 6.3; Value2: 6.3V; TaMin_C: -55; TaMax_C: 125; AEC Category: Q200
J1 = FTR-110-51-S-D-06: Header, 1.27mm, 10x2, Tin, SMT; Manufacturer: Samtec; SymbolCreator: a0412235; Pitch_mm: 1.27; Gender: Male; Shrouded: N; Row_Count: 2; RowSpacing_mm: 2.54; Current_A: 3.1; Cert_UL: Y
J2 = DF40HC(4.0)-60DS-0.4V(51): Receptacle, 0.4mm, 30x2, Gold, SMT; Manufacturer: Hirose Electric Co. Ltd.; SymbolCreator: Altium; Pitch_mm: 0.4; Gender: Female; Row_Count: 2; Current_A: 0.3; Voltage_V: 30; Cert_UL: Y
J3 = PEC06SAAN: Header, 100mil, 6x1, Tin, TH; Manufacturer: Sullins Connector Solutions; SymbolCreator: a0412235
J4 J5 = SSW-110-23-F-D: Connector, Receptacle, 100mil, 10x2, Gold plated, TH; Manufacturer: Samtec; SymbolCreator: a0412235
J9 = PEC01DAAN: Header, 2.54mm, 1x2, Tin, Black, TH; Manufacturer: Sullins Connector Solutions; SymbolCreator: a0412235; Pitch_mm: 2.54; Gender: Male; Shrouded: N; Row_Count: 2; Current_A: 3; Voltage_V: 1800; Cert_UL: Y
R1-R3 R11 R215 R216 = CRCW04024K70JNED: RES, 4.7 k, 5%, 0.063 W, 0402; Manufacturer: Vishay-Dale; CompType: Resistor; Value: 4.7k; Res_ohm: 4700; Value_Code: 4k70; Tolerance_%: 5; Power_W: 0.063; Value2: 0.063W; VDC_V: 50; TempCo: 200 ppm/C; EIA_Code: E24; U/M: EA
R4-R8 R12 R13 R170 R171 R186 R187 = CRCW04020000Z0ED: RES, 0, 5%, 0.063 W, 0402; Manufacturer: Vishay-Dale; CompType: Resistor; Value: 0; Value_Code: 0000; Tolerance_%: 5; Power_W: 0.063; Value2: 0.063W; VDC_V: 50; TempCo: 200 ppm/C; EIA_Code: E24; U/M: EA; AEC Category: Q200
R9 = CRCW0402100RJNED: RES, 100, 5%, 0.063 W, 0402; Manufacturer: Vishay-Dale; CompType: Resistor; Value: 100; Value_Code: 100R; Tolerance_%: 5; Power_W: 0.063; Value2: 0.063W; VDC_V: 50; TempCo: 200 ppm/C; SizeArea_mm2: 0.5; SizeX_mm: 1; SizeZ_mm: 0.6; EIA_Code: E24; U/M: EA; AEC Category: Q200
R10 = CRCW04021K00JNED: RES, 1.0 k, 5%, 0.063 W, 0402; Manufacturer: Vishay-Dale; CompType: Resistor; Value: 1.0k; Res_ohm: 1000; Value_Code: 1k00; Tolerance_%: 5; Power_W: 0.063; Value2: 0.063W; VDC_V: 50; TempCo: 200 ppm/C; EIA_Code: E24; U/M: EA; AEC Category: Q200
R55 R76 = CRCW040210K0JNED: RES, 10 k, 5%, 0.063 W, 0402; Manufacturer: Vishay-Dale; CompType: Resistor; Value: 10k; Res_ohm: 10000; Value_Code: 10k0; Tolerance_%: 5; Power_W: 0.063; Value2: 0.063W; VDC_V: 50; TempCo: 200 ppm/C; EIA_Code: E24; U/M: EA; SizeArea_mm2: 0.5; SizeX_mm: 1; SizeZ_mm: 0.6; AEC Category: Q200
R162 R168 R213 R214 = CRCW040210K0JNED: as R103 on sheet AMIC110 ICE EVM_BootConfig
R172 = CRCW0402100KJNED: as R122 on sheet AMIC110 ICE EVM_BootConfig
R173 R176 R177 = CRCW040251K0JNED: RES, 51 k, 5%, 0.063 W, 0402; Manufacturer: Vishay-Dale; CompType: Resistor; Value: 51k; Res_ohm: 51000; Value_Code: 51k0; Tolerance_%: 5; Power_W: 0.063; Value2: 0.063W; VDC_V: 50; TempCo: 200 ppm/C; SizeArea_mm2: 0.5; SizeX_mm: 1; SizeZ_mm: 0.6; EIA_Code: E24; U/M: EA; AEC Category: Q200
R174 R175 = CRCW040233K0JNED: RES, 33 k, 5%, 0.063 W, 0402; Manufacturer: Vishay-Dale; CompType: Resistor; Value: 33k; Res_ohm: 33000; Value_Code: 33k0; Tolerance_%: 5; Power_W: 0.063; Value2: 0.063W; VDC_V: 50; TempCo: 200 ppm/C; SizeArea_mm2: 0.5; SizeX_mm: 1; SizeZ_mm: 0.6; EIA_Code: E24; U/M: EA; AEC Category: Q200
R180 R181 = CRCW060310K0JNEA: RES, 10 k, 5%, 0.1 W, 0603; Manufacturer: Vishay-Dale; CompType: Resistor; Value: 10k; Res_ohm: 10000; Value_Code: 10k0; Tolerance_%: 5; Power_W: 0.1; Value2: 0.1W; VDC_V: 75; TempCo: 200 ppm/C; SizeArea_mm2: 1.28; SizeX_mm: 1.6; SizeY_mm: 0.8; SizeZ_mm: 1; EIA_Code: E24; U/M: EA; AEC Category: Q200
R184 R185 = CRCW06031K00JNEA: RES, 1.0 k, 5%, 0.1 W, 0603; Manufacturer: Vishay-Dale; CompType: Resistor; Value: 1.0k; Res_ohm: 1000; Value_Code: 1k00; Tolerance_%: 5; Power_W: 0.1; Value2: 0.1W; VDC_V: 75; TempCo: 200 ppm/C; SizeArea_mm2: 1.28; SizeX_mm: 1.6; SizeY_mm: 0.8; SizeZ_mm: 1; EIA_Code: E24; U/M: EA; AEC Category: Q200
S1 = B3U-1000P: SWITCH TACTILE SPST-NO 0.05A 12V; Manufacturer: Omron Electronic Components; SymbolCreator: a0412235; VDC_V: 12; SwitchFunction: Off-Mom; PositionCount: 1; CurrentRating_mA: 50
U12 = SN74LVC2G241YZPR: Dual Buffer and Driver With 3-State Output, YZP0008ADAD; Manufacturer: Texas Instruments; SymbolCreator: Altium; SizeArea_mm2: 2.8125; SizeAreaWB_mm2: 7.3125; SizeX_mm: 1.25; SizeY_mm: 2.25; SizeZ_mm: 0.5; CompType: IC; U/M: EA
U13-U15 = SN74CB3Q3245RGYR: 8-BIT FET BUS SWITCH 2.5-V/3.3-V LOW-VOLTAGE HIGH-BANDWIDTH BUS SWITCH, RGY0020A; Manufacturer: Texas Instruments; SymbolCreator: Altium; SizeArea_mm2: 15.75; SizeAreaWB_mm2: 24.75; SizeX_mm: 3.5; SizeY_mm: 4.5; SizeZ_mm: 1; CompType: IC; U/M: EA

## Sheet AMIC110 ICE EVM_Led.SchDoc
size 431 x 279 mm; Date: Not shown in title block; ApprovedBy: Not shown in title block; CheckedBy: Not shown in title block; Author: Not shown in title block; CompanyName: Not shown in title block; Engineer: Not shown in title block; Organization: Not shown in title block; Address1: Not shown in title block; Address2: Not shown in title block; Address3: Not shown in title block; Address4: Not shown in title block; DocumentNumber: 1; Revision: Use project parameter SCH_Rev; SheetNumber: 8; SheetTotal: 1; PageSetup: Record=PageOptions¦CenterHorizontal=True¦CenterVertical=True¦PrintScale=1.00¦XCorrection=1.00¦YCorrection=1.00¦PrintKind=0¦BorderSize=5000000¦LeftOffset=0¦BottomOffset=0¦Orientation=2¦PaperLength=1000¦PaperWidth=1000¦Scale=100¦PaperSource=15¦PrintQuality=600¦MediaType=1¦DitherType=10¦PaperKind=Letter¦PrintScaleMode=1
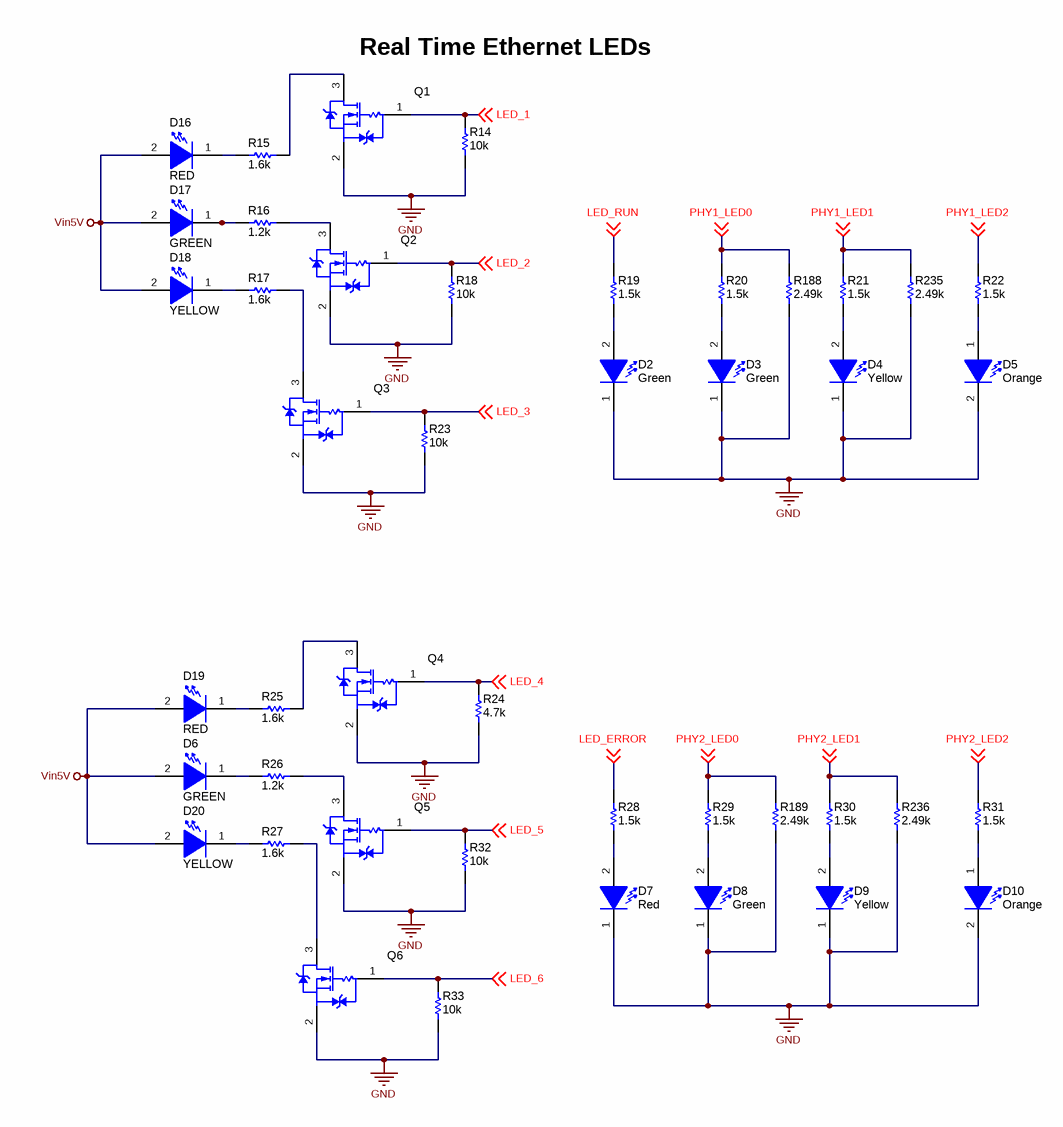
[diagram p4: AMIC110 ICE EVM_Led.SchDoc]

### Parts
D2  value Green  [WL-SMCW_GREEN]  (hidden comment: 150060VS75000)
D3  value Green  [WL-SMCW_GREEN]  (hidden comment: 150060VS75000)
D4  value Yellow  [WL-SMCW_YELLOW]  (hidden comment: 150060YS75000)
D5  value Orange  [VLMx1500_Orange]  (hidden comment: VLMO1500-GS08)
D6  value GREEN  [APTD1608]  (hidden comment: APTD1608LZGCK)
D7  value Red  [WL-SMCW_RED]  (hidden comment: 150060RS75000)
D8  value Green  [WL-SMCW_GREEN]  (hidden comment: 150060VS75000)
D9  value Yellow  [WL-SMCW_YELLOW]  (hidden comment: 150060YS75000)
D10  value Orange  [VLMx1500_Orange]  (hidden comment: VLMO1500-GS08)
D16  value RED  [APTD1608]  (hidden comment: APTD1608LSECK/J3-PF)
D17  value GREEN  [APTD1608]  (hidden comment: APTD1608LZGCK)
D18  value YELLOW  [APTD1608]  (hidden comment: APTD1608LSYCK/J3-PF)
D19  value RED  [APTD1608]  (hidden comment: APTD1608LSECK/J3-PF)
D20  value YELLOW  [APTD1608]  (hidden comment: APTD1608LSYCK/J3-PF)
Q1  CSD13383F4  [YJC0003A]  (value not drawn)
Q2  CSD13383F4  [YJC0003A]  (value not drawn)
Q3  CSD13383F4  [YJC0003A]  (value not drawn)
Q4  CSD13383F4  [YJC0003A]  (value not drawn)
Q5  CSD13383F4  [YJC0003A]  (value not drawn)
Q6  CSD13383F4  [YJC0003A]  (value not drawn)
R14  ValueDisplayed: 10k  [0402L]  (hidden comment: CRCW040210K0JNED)
R15  ValueDisplayed: 1.6k  [0402L]  (hidden comment: CRCW04021K60JNED)
R16  ValueDisplayed: 1.2k  [0402L]  (hidden comment: CRCW04021K20JNED)
R17  ValueDisplayed: 1.6k  [0402L]  (hidden comment: CRCW04021K60JNED)
R18  ValueDisplayed: 10k  [0402L]  (hidden comment: CRCW040210K0JNED)
R19  ValueDisplayed: 1.5k  [0402L]  (hidden comment: CRCW04021K50JNED)
R20  ValueDisplayed: 1.5k  [0402L]  (hidden comment: CRCW04021K50JNED)
R21  ValueDisplayed: 1.5k  [0402L]  (hidden comment: CRCW04021K50JNED)
R22  ValueDisplayed: 1.5k  [0402L]  (hidden comment: CRCW04021K50JNED)
R23  ValueDisplayed: 10k  [0402L]  (hidden comment: CRCW040210K0JNED)
R24  ValueDisplayed: 4.7k  [0402L]  (hidden comment: CRCW04024K70JNED)
R25  ValueDisplayed: 1.6k  [0402L]  (hidden comment: CRCW04021K60JNED)
R26  ValueDisplayed: 1.2k  [0402L]  (hidden comment: CRCW04021K20JNED)
R27  ValueDisplayed: 1.6k  [0402L]  (hidden comment: CRCW04021K60JNED)
R28  ValueDisplayed: 1.5k  [0402L]  (hidden comment: CRCW04021K50JNED)
R29  ValueDisplayed: 1.5k  [0402L]  (hidden comment: CRCW04021K50JNED)
R30  ValueDisplayed: 1.5k  [0402L]  (hidden comment: CRCW04021K50JNED)
R31  ValueDisplayed: 1.5k  [0402L]  (hidden comment: CRCW04021K50JNED)
R32  ValueDisplayed: 10k  [0402L]  (hidden comment: CRCW040210K0JNED)
R33  ValueDisplayed: 10k  [0402L]  (hidden comment: CRCW040210K0JNED)
R188  ValueDisplayed: 2.49k  [0402L]  (hidden comment: CRCW04022K49FKED)
R189  ValueDisplayed: 2.49k  [0402L]  (hidden comment: CRCW04022K49FKED)
R235  ValueDisplayed: 2.49k  [0402L]  (hidden comment: CRCW04022K49FKED)
R236  ValueDisplayed: 2.49k  [0402L]  (hidden comment: CRCW04022K49FKED)

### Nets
GND: D2.1(K) D3.1(K) D4.1(K) D5.2(K) D7.1(K) D8.1(K) D9.1(K) D10.2(K) Q1.2(S) Q2.2(S) Q3.2(S) Q4.2(S) Q5.2(S) Q6.2(S) R14.1 R18.1 R23.1 R24.1 R32.1 R33.1 R188.1 R189.1 R235.1 R236.1
Vin5V: D6.2(A) D16.2(A) D17.2(A) D18.2(A) D19.2(A) D20.2(A)
LED_1: Q1.1(G) R14.2 ; off-sheet LED_1
LED_2: Q2.1(G) R18.2 ; off-sheet LED_2
LED_3: Q3.1(G) R23.2 ; off-sheet LED_3
LED_4: Q4.1(G) R24.2 ; off-sheet LED_4
LED_5: Q5.1(G) R32.2 ; off-sheet LED_5
LED_6: Q6.1(G) R33.2 ; off-sheet LED_6
LED_ERROR: R28.1 ; off-sheet LED_ERROR
LED_RUN: R19.2 ; off-sheet LED_RUN
PHY1_LED0: R20.2 R188.2 ; off-sheet PHY1_LED0
PHY1_LED1: R21.2 R235.2 ; off-sheet PHY1_LED1
PHY1_LED2: R22.2 ; off-sheet PHY1_LED2
PHY2_LED0: R29.2 R189.2 ; off-sheet PHY2_LED0
PHY2_LED1: R30.2 R236.2 ; off-sheet PHY2_LED1
PHY2_LED2: R31.2 ; off-sheet PHY2_LED2
NetD2_2: D2.2(A) R19.1
NetD3_2: D3.2(A) R20.1
NetD4_2: D4.2(A) R21.1
NetD5_1: D5.1(A) R22.1
NetD6_1: D6.1(K) R26.1
NetD7_2: D7.2(A) R28.2
NetD8_2: D8.2(A) R29.1
NetD9_2: D9.2(A) R30.1
NetD10_1: D10.1(A) R31.1
NetD16_1: D16.1(K) R15.1
NetD17_1: D17.1(K) R16.1
NetD18_1: D18.1(K) R17.1
NetD19_1: D19.1(K) R25.1
NetD20_1: D20.1(K) R27.1
NetQ1_3: Q1.3(D) R15.2
NetQ2_3: Q2.3(D) R16.2
NetQ3_3: Q3.3(D) R17.2
NetQ4_3: Q4.3(D) R25.2
NetQ5_3: Q5.3(D) R26.2
NetQ6_3: Q6.3(D) R27.2

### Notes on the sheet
- (near Q1) Real Time Ethernet LEDs

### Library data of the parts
D2 D3 D8 = 150060VS75000: LED, Green, SMD; Manufacturer: Wurth Elektronik; Type: AlInGaP; Vf_V: 2; Value2: 2V; Io_A: 0.02; Value1: W; U/M: EA
D4 D9 = 150060YS75000: LED, Yellow, SMD; Manufacturer: Wurth Elektronik; Type: AlInGaP; Vf_V: 2; Value2: 2V; Io_A: 0.02; Value1: W; U/M: EA
D5 D10 = VLMO1500-GS08: LED, Orange, SMD; Manufacturer: Vishay-Semiconductor; Type: AlInGaP; Vf_V: 2; Value2: 2V; Io_A: 0.02; Value1: W; U/M: EA
D6 D17 = APTD1608LZGCK: LED, GREEN SMD; Manufacturer: Kingbright; Type: AlInGalnP; Vf_V: 2.65; Io_A: 0.02; U/M: EA
D7 = 150060RS75000: LED, Red, SMD; Manufacturer: Wurth Elektronik; Type: AlInGaP; Vf_V: 2; Value2: 2V; Io_A: 0.03; Vr_V: 5; Tjmax_C: 85; Power_TotalModule: 0.072; Value1: 0.072W; Angle: 140; U/M: EA
D16 D19 = APTD1608LSECK/J3-PF: LED, RED SMD; Manufacturer: Kingbright; Type: AlInGalnP; Vf_V: 1.8; Io_A: 0.02; U/M: EA
D18 D20 = APTD1608LSYCK/J3-PF: LED, YELLOW SMD; Manufacturer: Kingbright; Type: AlInGalnP; Vf_V: 1.85; Io_A: 0.02; U/M: EA
Q1-Q6 = CSD13383F4: MOSFET, N-CH, 12 V, 2.9 A, YJC0003A; Manufacturer: Texas Instruments; Alternate Manufacturer: None; SymbolCreator: a0411947; U/M: EA; ChType: N; Value: 12V; VdsMax_V: 12; Value1: 0.044 ohm; Rdson45_ohm: 0.044; Value2: 2 nC; QgTyp_nC: 2; Vgs_V: 10; IdsMax_A: 2.9; AEC Category: Q101
R14 R18 R23 R32 R33 = CRCW040210K0JNED: RES, 10 k, 5%, 0.063 W, 0402; Manufacturer: Vishay-Dale; CompType: Resistor; Value: 10k; Res_ohm: 10000; Value_Code: 10k0; Tolerance_%: 5; Power_W: 0.063; Value2: 0.063W; VDC_V: 50; TempCo: 200 ppm/C; EIA_Code: E24; U/M: EA; AEC Category: Q200; SizeArea_mm2: 0.5; SizeX_mm: 1; SizeZ_mm: 0.6
R15 R17 R25 R27 = CRCW04021K60JNED: RES, 1.6k, 5%, 0.063 W, 0402; Manufacturer: Vishay-Dale; CompType: Resistor; Value_Code: 1.6kR; Tolerance_%: 5; Power_W: 0.063; Value2: 0.063W; VDC_V: 50; TempCo: 200 ppm/c; EIA_Code: E24; U/M: EA; AEC Category: Q200
R16 R26 = CRCW04021K20JNED: RES, 1.2k, 5%, 0.063 W, 0402; Manufacturer: Vishay-Dale; CompType: Resistor; Value_Code: 1.2kR; Tolerance_%: 5; Power_W: 0.063; Value2: 0.063W; VDC_V: 50; TempCo: 200 ppm/c; EIA_Code: E24; U/M: EA; AEC Category: Q200
R19-R22 R28-R31 = CRCW04021K50JNED: RES, 1.5 k, 5%, 0.063 W, 0402; Manufacturer: Vishay-Dale; CompType: Resistor; Value: 1.5k; Res_ohm: 1500; Value_Code: 1k50; Tolerance_%: 5; Power_W: 0.063; Value2: 0.063W; VDC_V: 50; TempCo: 200 ppm/C; EIA_Code: E24; U/M: EA; AEC Category: Q200
R24 = CRCW04024K70JNED: RES, 4.7 k, 5%, 0.063 W, 0402; Manufacturer: Vishay-Dale; CompType: Resistor; Value: 4.7k; Res_ohm: 4700; Value_Code: 4k70; Tolerance_%: 5; Power_W: 0.063; Value2: 0.063W; VDC_V: 50; TempCo: 200 ppm/C; EIA_Code: E24; U/M: EA; AEC Category: Q200; SizeArea_mm2: 0.5; SizeX_mm: 1; SizeZ_mm: 0.6
R188 R189 R235 R236 = CRCW04022K49FKED: RES, 2.49 k, 1%, 0.063 W, 0402; Manufacturer: Vishay-Dale; CompType: Resistor; Value: 2.49k; Res_ohm: 2490; Value_Code: 2k49; Tolerance_%: 1; Power_W: 0.063; Value2: 0.063W; VDC_V: 50; TempCo: 100 ppm/C; EIA_Code: E96; U/M: EA; SizeArea_mm2: 0.5; SizeZ_mm: 0.6; AEC Category: Q200

## Sheet AMIC110 ICE EVM_Memory.SchDoc
size 431 x 279 mm; Date: Not shown in title block; ApprovedBy: Not shown in title block; CheckedBy: Not shown in title block; Author: Not shown in title block; CompanyName: Not shown in title block; Engineer: Not shown in title block; Organization: Not shown in title block; Address1: Not shown in title block; Address2: Not shown in title block; Address3: Not shown in title block; Address4: Not shown in title block; DocumentNumber: 1; Revision: Use project parameter SCH_Rev; SheetNumber: 10; SheetTotal: 1; PageSetup: Record=PageOptions¦CenterHorizontal=True¦CenterVertical=True¦PrintScale=1.00¦XCorrection=1.00¦YCorrection=1.00¦PrintKind=0¦BorderSize=5000000¦LeftOffset=0¦BottomOffset=0¦Orientation=2¦PaperLength=1000¦PaperWidth=1000¦Scale=100¦PaperSource=15¦PrintQuality=600¦MediaType=1¦DitherType=10¦PaperKind=Letter¦PrintScaleMode=1
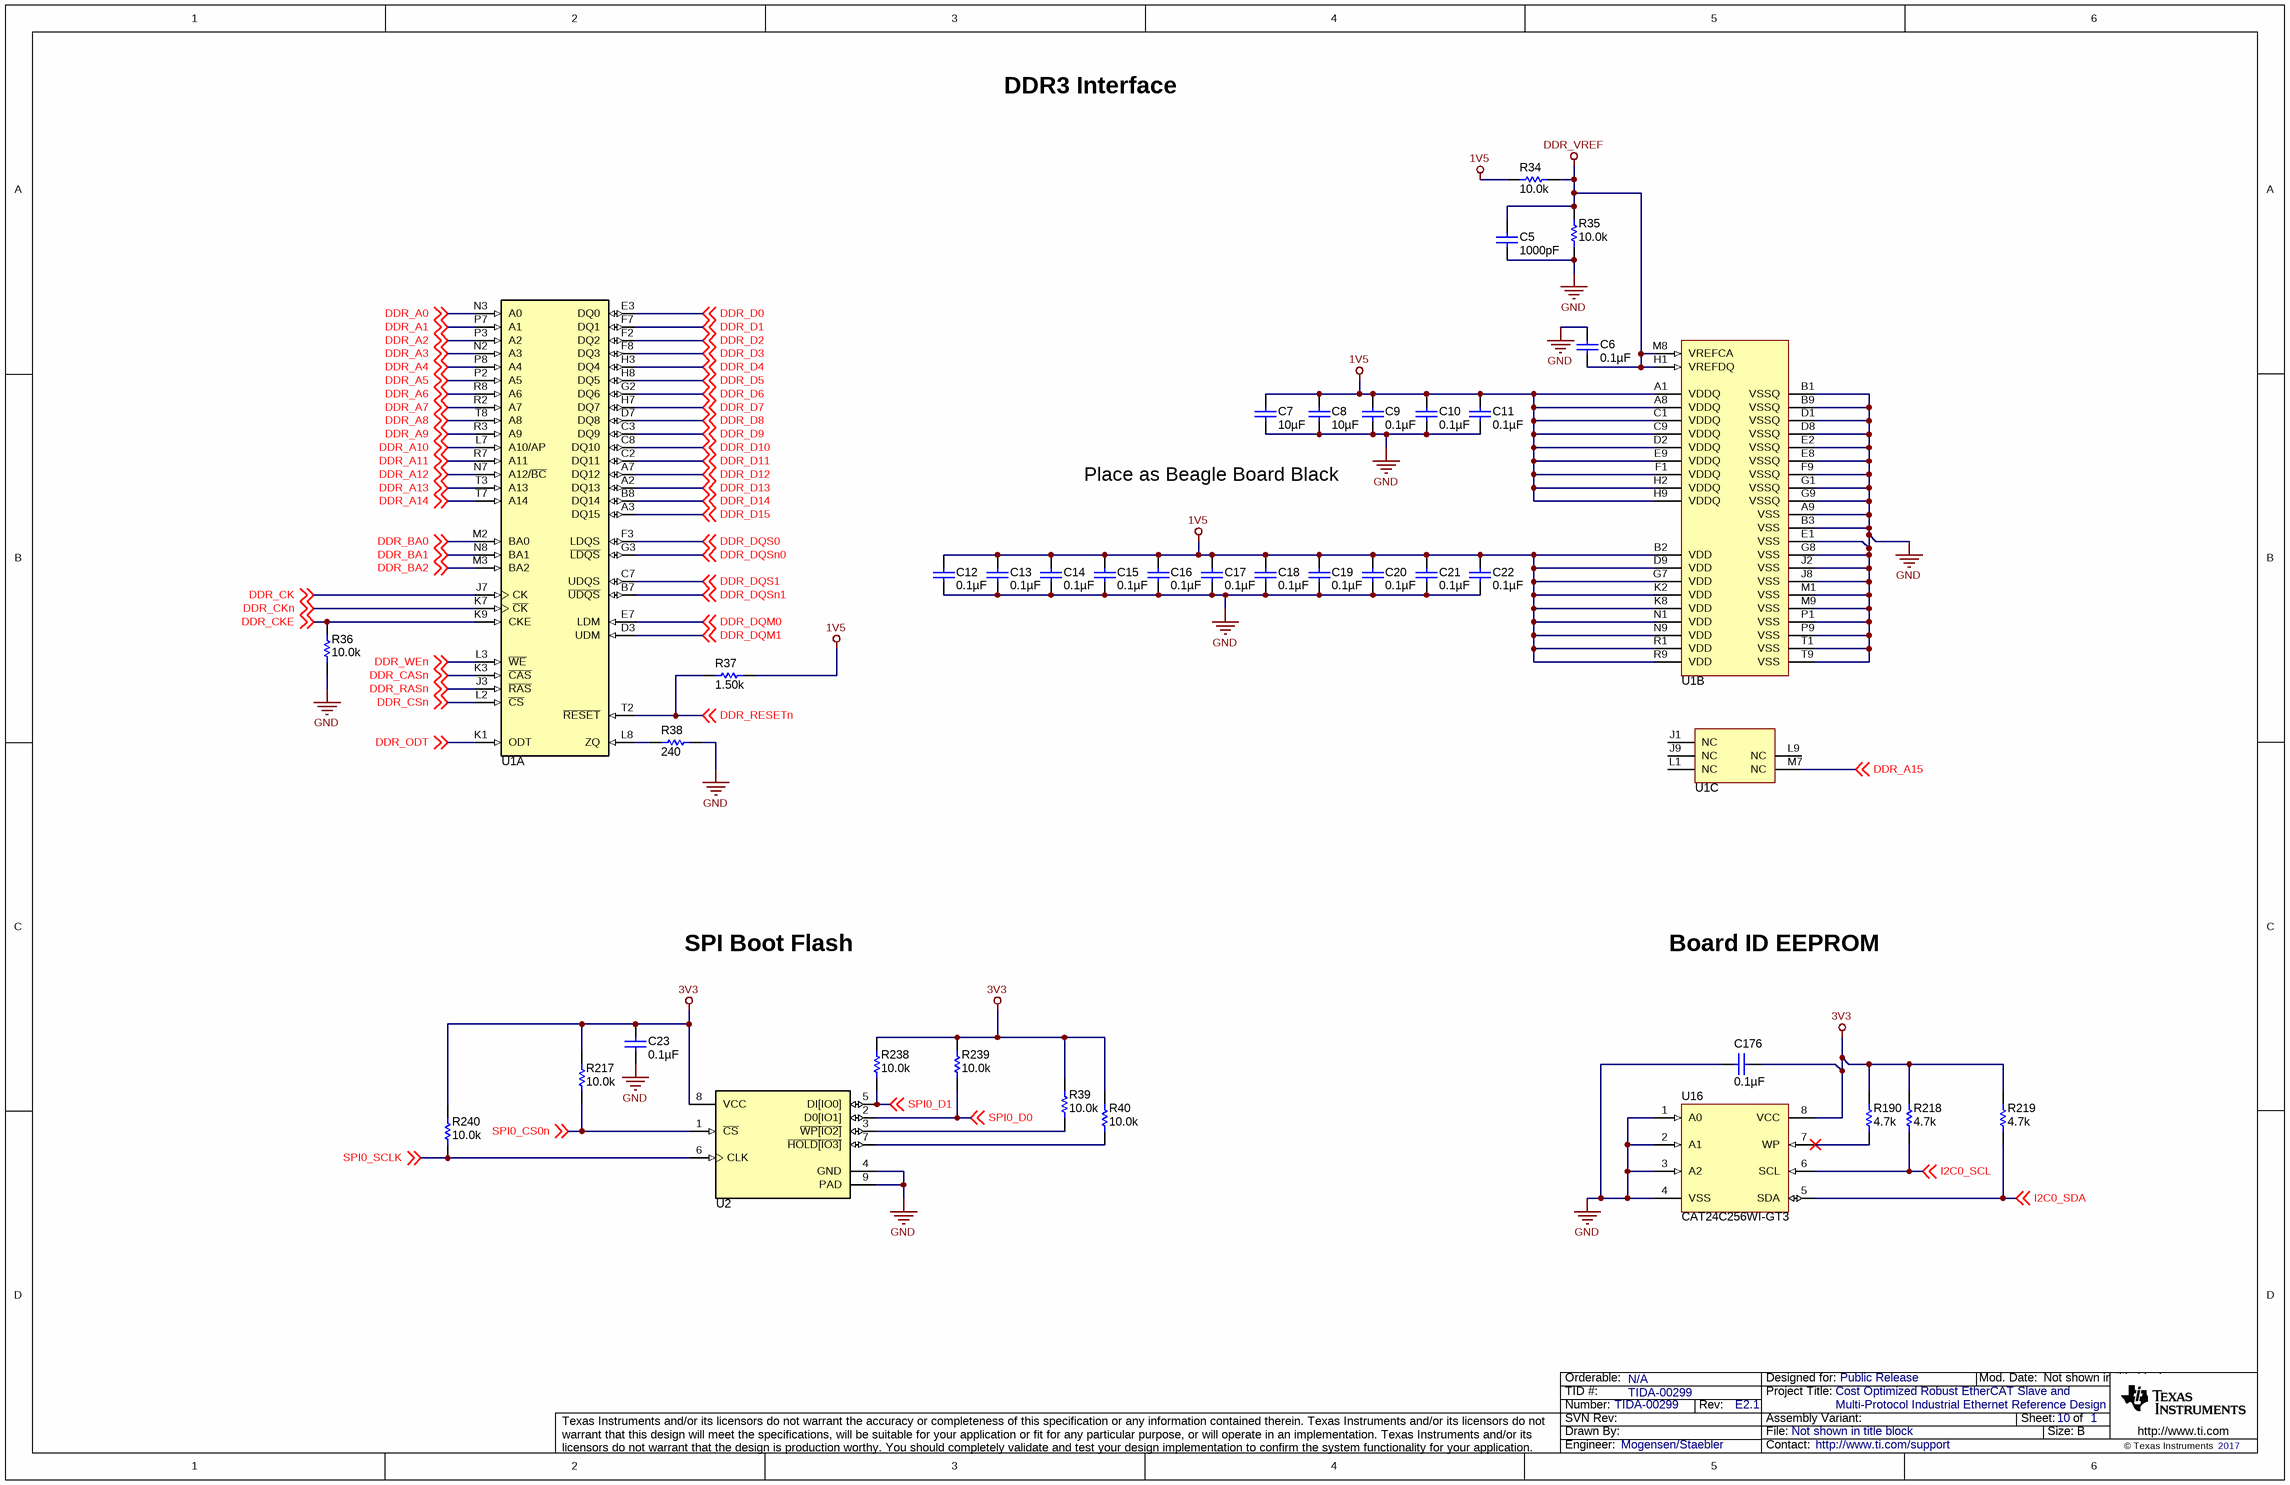
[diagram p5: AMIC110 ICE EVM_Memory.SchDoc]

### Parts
C5  ValueDisplayed: 1000pF  [0402]  (hidden comment: GRM155R71C102KA01D)
C6  ValueDisplayed: 0.1µF  [0402]  (hidden comment: GRM155R70J104KA01D)
C7  ValueDisplayed: 10µF  [0805_HV]  (hidden comment: 885012207026)
C8  ValueDisplayed: 10µF  [0805_HV]  (hidden comment: 885012207026)
C9  ValueDisplayed: 0.1µF  [0402]  (hidden comment: 885012205037)
C10  ValueDisplayed: 0.1µF  [0402]  (hidden comment: 885012205037)
C11  ValueDisplayed: 0.1µF  [0402]  (hidden comment: 885012205037)
C12  ValueDisplayed: 0.1µF  [0402]  (hidden comment: 885012205037)
C13  ValueDisplayed: 0.1µF  [0402]  (hidden comment: 885012205037)
C14  ValueDisplayed: 0.1µF  [0402]  (hidden comment: 885012205037)
C15  ValueDisplayed: 0.1µF  [0402]  (hidden comment: 885012205037)
C16  ValueDisplayed: 0.1µF  [0402]  (hidden comment: 885012205037)
C17  ValueDisplayed: 0.1µF  [0402]  (hidden comment: 885012205037)
C18  ValueDisplayed: 0.1µF  [0402]  (hidden comment: 885012205037)
C19  ValueDisplayed: 0.1µF  [0402]  (hidden comment: 885012205037)
C20  ValueDisplayed: 0.1µF  [0402]  (hidden comment: 885012205037)
C21  ValueDisplayed: 0.1µF  [0402]  (hidden comment: 885012205037)
C22  ValueDisplayed: 0.1µF  [0402]  (hidden comment: 885012205037)
C23  ValueDisplayed: 0.1µF  [0402]  (hidden comment: GRM155R70J104KA01D)
C176  ValueDisplayed: 0.1µF  [0402]  (hidden comment: GRM155R71A104KA01D)
R34  ValueDisplayed: 10.0k  [0402]  (hidden comment: CRCW040210K0FKED)
R35  ValueDisplayed: 10.0k  [0402]  (hidden comment: CRCW040210K0FKED)
R36  ValueDisplayed: 10.0k  [0402]  (hidden comment: CRCW040210K0FKED)
R37  ValueDisplayed: 1.50k  [0402]  (hidden comment: CRCW04021K50FKED)
R38  ValueDisplayed: 240  [0402]  (hidden comment: ERJ-2RKF2400X)
R39  ValueDisplayed: 10.0k  [0402L]  (hidden comment: CRCW040210K0FKED)
R40  ValueDisplayed: 10.0k  [0402]  (hidden comment: CRCW040210K0FKED)
R190  ValueDisplayed: 4.7k  [0402L]  (hidden comment: CRCW04024K70JNED)
R217  ValueDisplayed: 10.0k  [0402L]  (hidden comment: CRCW040210K0FKED)
R218  ValueDisplayed: 4.7k  [0402]  (hidden comment: CRCW04024K70JNED)
R219  ValueDisplayed: 4.7k  [0402]  (hidden comment: CRCW04024K70JNED)
R238  ValueDisplayed: 10.0k  [0402L]  (hidden comment: CRCW040210K0FKED)
R239  ValueDisplayed: 10.0k  [0402L]  (hidden comment: CRCW040210K0FKED)
R240  ValueDisplayed: 10.0k  [0402L]  (hidden comment: CRCW040210K0FKED)
U1  MT41K256M16HA-125 IT:E  [96-FBGA]  (value not drawn)  (parts A,B,C of 3)
U2  W25Q64FVZPIG  [Winbond-WSON6x5_Code P]  (value not drawn)
U16  CAT24C256WI-GT3  [SOIC-8]

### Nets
1V5: C7.1 C8.1 C9.1 C10.1 C11.1 C12.1 C13.1 C14.1 C15.1 C16.1 C17.1 C18.1 C19.1 C20.1 C21.1 C22.1 R34.1 R37.1 U1.A1(VDDQ) U1.A8(VDDQ) U1.B2(VDD) U1.C1(VDDQ) U1.C9(VDDQ) U1.D2(VDDQ) U1.D9(VDD) U1.E9(VDDQ) U1.F1(VDDQ) U1.G7(VDD) U1.H2(VDDQ) U1.H9(VDDQ) U1.K2(VDD) U1.K8(VDD) U1.N1(VDD) U1.N9(VDD) U1.R1(VDD) U1.R9(VDD)
3V3: C23.2 C176.2 R39.2 R40.2 R190.2 R217.2 R218.2 R219.2 R238.2 R239.2 R240.2 U2.8(VCC) U16.8(VCC)
DDR_VREF: C5.1 C6.1 R34.2 R35.2 U1.H1(VREFDQ) U1.M8(VREFCA)
GND: C5.2 C6.2 C7.2 C8.2 C9.2 C10.2 C11.2 C12.2 C13.2 C14.2 C15.2 C16.2 C17.2 C18.2 C19.2 C20.2 C21.2 C22.2 C23.1 C176.1 R35.1 R36.1 R38.2 U1.A9(VSS) U1.B1(VSSQ) U1.B3(VSS) U1.B9(VSSQ) U1.D1(VSSQ) U1.D8(VSSQ) U1.E1(VSS) U1.E2(VSSQ) U1.E8(VSSQ) U1.F9(VSSQ) U1.G1(VSSQ) U1.G8(VSS) U1.G9(VSSQ) U1.J2(VSS) U1.J8(VSS) U1.M1(VSS) U1.M9(VSS) U1.P1(VSS) U1.P9(VSS) U1.T1(VSS) U1.T9(VSS) U2.4(GND) U2.9(PAD) U16.1(A0) U16.2(A1) U16.3(A2) U16.4(VSS)
DDR_A0: U1.N3(A0) ; off-sheet DDR_A0
DDR_A1: U1.P7(A1) ; off-sheet DDR_A1
DDR_A2: U1.P3(A2) ; off-sheet DDR_A2
DDR_A3: U1.N2(A3) ; off-sheet DDR_A3
DDR_A4: U1.P8(A4) ; off-sheet DDR_A4
DDR_A5: U1.P2(A5) ; off-sheet DDR_A5
DDR_A6: U1.R8(A6) ; off-sheet DDR_A6
DDR_A7: U1.R2(A7) ; off-sheet DDR_A7
DDR_A8: U1.T8(A8) ; off-sheet DDR_A8
DDR_A9: U1.R3(A9) ; off-sheet DDR_A9
DDR_A10: U1.L7(A10/AP) ; off-sheet DDR_A10
DDR_A11: U1.R7(A11) ; off-sheet DDR_A11
DDR_A12: U1.N7(A12/~{BC}) ; off-sheet DDR_A12
DDR_A13: U1.T3(A13) ; off-sheet DDR_A13
DDR_A14: U1.T7(A14) ; off-sheet DDR_A14
DDR_A15: U1.M7(NC) ; off-sheet DDR_A15
DDR_BA0: U1.M2(BA0) ; off-sheet DDR_BA0
DDR_BA1: U1.N8(BA1) ; off-sheet DDR_BA1
DDR_BA2: U1.M3(BA2) ; off-sheet DDR_BA2
DDR_CASn: U1.K3(~{CAS}) ; off-sheet DDR_CASn
DDR_CK: U1.J7(CK) ; off-sheet DDR_CK
DDR_CKE: R36.2 U1.K9(CKE) ; off-sheet DDR_CKE
DDR_CKn: U1.K7(~{CK}) ; off-sheet DDR_CKn
DDR_CSn: U1.L2(~{CS}) ; off-sheet DDR_CSn
DDR_D0: U1.E3(DQ0) ; off-sheet DDR_D0
DDR_D1: U1.F7(DQ1) ; off-sheet DDR_D1
DDR_D2: U1.F2(DQ2) ; off-sheet DDR_D2
DDR_D3: U1.F8(DQ3) ; off-sheet DDR_D3
DDR_D4: U1.H3(DQ4) ; off-sheet DDR_D4
DDR_D5: U1.H8(DQ5) ; off-sheet DDR_D5
DDR_D6: U1.G2(DQ6) ; off-sheet DDR_D6
DDR_D7: U1.H7(DQ7) ; off-sheet DDR_D7
DDR_D8: U1.D7(DQ8) ; off-sheet DDR_D8
DDR_D9: U1.C3(DQ9) ; off-sheet DDR_D9
DDR_D10: U1.C8(DQ10) ; off-sheet DDR_D10
DDR_D11: U1.C2(DQ11) ; off-sheet DDR_D11
DDR_D12: U1.A7(DQ12) ; off-sheet DDR_D12
DDR_D13: U1.A2(DQ13) ; off-sheet DDR_D13
DDR_D14: U1.B8(DQ14) ; off-sheet DDR_D14
DDR_D15: U1.A3(DQ15) ; off-sheet DDR_D15
DDR_DQM0: U1.E7(LDM) ; off-sheet DDR_DQM0
DDR_DQM1: U1.D3(UDM) ; off-sheet DDR_DQM1
DDR_DQS0: U1.F3(LDQS) ; off-sheet DDR_DQS0
DDR_DQS1: U1.C7(UDQS) ; off-sheet DDR_DQS1
DDR_DQSn0: U1.G3(~{LDQS}) ; off-sheet DDR_DQSn0
DDR_DQSn1: U1.B7(~{UDQS}) ; off-sheet DDR_DQSn1
DDR_ODT: U1.K1(ODT) ; off-sheet DDR_ODT
DDR_RASn: U1.J3(~{RAS}) ; off-sheet DDR_RASn
DDR_RESETn: R37.2 U1.T2(~{RESET}) ; off-sheet DDR_RESETn
DDR_WEn: U1.L3(~{WE}) ; off-sheet DDR_WEn
I2C0_SCL: R218.1 U16.6(SCL) ; off-sheet I2C0_SCL
I2C0_SDA: R219.1 U16.5(SDA) ; off-sheet I2C0_SDA
SPI0_CS0n: R217.1 U2.1(~{CS}) ; off-sheet SPI0_CS0n
SPI0_D0: R239.1 U2.2(D0[IO1]) ; off-sheet SPI0_D0
SPI0_D1: R238.1 U2.5(DI[IO0]) ; off-sheet SPI0_D1
SPI0_SCLK: R240.1 U2.6(CLK) ; off-sheet SPI0_SCLK
NetR38_1: R38.1 U1.L8(ZQ)
NetR39_1: R39.1 U2.3(~{WP[IO2]})
NetR40_1: R40.1 U2.7(~{HOLD[IO3]})
NetR190_1: R190.1 U16.7(WP)

Not connected (* = marked no-connect by the designer): U1 J1(NC) J9(NC) L1(NC) L9(NC)

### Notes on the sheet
- DDR3 Interface
- Place as Beagle Board Black
- SPI Boot Flash
- Board ID EEPROM

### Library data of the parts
C5 = GRM155R71C102KA01D: CAP, CERM, 1000 pF, 16 V, +/- 10%, X7R, 0402; Manufacturer: MuRata; Polarized: N; CompType: Capacitor; Value: 1000pF; U/M: EA; Cap_F: 0.000000001; Tolerance_%: 10; Value1: Unknown; VDC_V: 16; Value2: 16V; TaMin_C: -55; TaMax_C: 125; AEC Category: Q200
C6 C23 = GRM155R70J104KA01D: as C3 on sheet AMIC110 ICE EVM_Interfaces
C7 C8 = 885012207026: CAP, CERM, 10 µF, 10 V, +/- 10%, X7R, 0805; Manufacturer: Wurth Elektronik; Polarized: N; CompType: Capacitor; Value: 10uF; U/M: EA; Cap_F: 0.00001; Tolerance_%: 10; Value1: Unknown; Value2: 10V; TaMin_C: -55; TaMax_C: 125; Cap_Case: 0805; AEC Category: Q200
C9-C22 = 885012205037: as C88 on sheet AMIC110 ICE EVM_BootConfig
C176 = GRM155R71A104KA01D: as C2 on sheet AMIC110 ICE EVM_Interfaces
R34-R36 R39 R40 R217 R238-R240 = CRCW040210K0FKED: RES, 10.0 k, 1%, 0.063 W, 0402; Manufacturer: Vishay-Dale; CompType: Resistor; Value: 10.0k; Res_ohm: 10000; Value_Code: 10k0; Tolerance_%: 1; Power_W: 0.063; Value2: 0.063W; VDC_V: 50; TempCo: 100 ppm/C; EIA_Code: E96; U/M: EA; AEC Category: Q200
R37 = CRCW04021K50FKED: RES, 1.50 k, 1%, 0.063 W, 0402; Manufacturer: Vishay-Dale; CompType: Resistor; Value: 1.50k; Res_ohm: 1500; Value_Code: 1k50; Tolerance_%: 1; Power_W: 0.063; Value2: 0.063W; VDC_V: 50; TempCo: 100 ppm/C; EIA_Code: E96; U/M: EA; AEC Category: Q200
R38 = ERJ-2RKF2400X: RES, 240, 1%, 0.1 W, AEC-Q200 Grade 0, 0402; Manufacturer: Panasonic; CompType: Resistor; Value: 240; Value_Code: 240R; Tolerance_%: 1; Power_W: 0.1; Value2: 0.1W; VDC_V: 50; TempCo: 100 ppm/C; U/M: EA; AEC Category: Q200; AEC Qualified: Y; AEC Grade: 0
R190 R218 R219 = CRCW04024K70JNED: as R1 on sheet AMIC110 ICE EVM_Interfaces
U1 = MT41K256M16HA-125 IT:E: 4GBIT DDR3 SDRAM, 96-FBGA; Manufacturer: Micron Technology; SymbolCreator: Altium
U2 = W25Q64FVZPIG: 3V 64 M-bit Serial Flash Memory With Dual/Quad SPI&QPI, WSON-8; Manufacturer: Winbond; SymbolCreator: Altium
U16 = CAT24C256WI-GT3: 256 kb I2C CMOS Serial EEPROM, SOIC-8; Manufacturer: ON Semiconductor; SymbolCreator: a0411947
